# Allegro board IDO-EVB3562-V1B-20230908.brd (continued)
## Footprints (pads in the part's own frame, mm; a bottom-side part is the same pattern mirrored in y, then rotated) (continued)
RJ45-TH_HR911105A
  round 3.25 hole 3.25 unplated: (-5.715,0) (5.715,0)
  round 1.27 hole 0.914: 1(-4.445,6.35) 2(-3.175,8.89) 3(-1.905,6.35) 4(-0.635,8.89) 5(0.635,6.35) 6(1.905,8.89) 7(3.175,6.35) 8(4.445,8.89) 9(-6.625,-4.9) 10(-4.085,-4.9) 11(4.085,-4.9) 12(6.625,-4.9)
  round 2.5 hole 1.7: 13(-7.745,3.05) 14(7.745,3.05)
RJ45-TH_HY911130A
  round 2.997 hole 3.251 unplated: (-5.715,0) (5.715,0)
  round 1.524 hole 0.889: 1(5.715,-8.89) 2(4.445,-6.35) 3(3.175,-8.89) 4(1.905,-6.35) 5(0.635,-8.89) 6(-0.635,-6.35) 7(-1.905,-8.89) 8(-3.175,-6.35) 9(-4.445,-8.89) 10(-5.715,-6.35)
  round 1.651 hole 1.016: 11(6.624,4.9) 12(4.084,4.9) 13(-4.084,4.9) 14(-6.624,4.9)
  round 2.54 hole 1.651: SH1(-7.846,-3.051) SH2(7.846,-3.051)
RN_0402X4
  rect 0.5x0.399 smd: 1(-0.5,0.8) 4(-0.5,-0.8) 5(0.5,-0.8) 8(0.5,0.8)
  rect 0.5x0.3 smd: 2(-0.5,0.25) 3(-0.5,-0.25) 6(0.5,-0.25) 7(0.5,0.25)
SIM-91288-021
  rect 1.829x1.397 smd: C1(-0.251,12.319) C2(-0.251,9.779) C3(-0.251,7.239) C5(-23.422,12.319) C6(-23.422,9.779) C7(-23.422,7.239) CD1(-0.251,-0.051) CD2(-23.422,-0.051)
SIP2-10D-510
  round 1.4 hole 0.991: 1(-2.591,0) 2(2.591,0)
SMAF
  rect 1.43x1.53 smd: A(-1.84,0) C(1.84,0)
SMB_DO-214AA
  rect 1.65x1.95 smd: A(2.2,0) C(-2.2,0)
SMD1812
  rect 2.032x3.302 smd: 1(-2.159,0) 2(2.159,0)
SOD523
  rect 0.65x0.5 smd: A(0.9,0) C(-0.9,0)
SOD-123F
  rect 0.94x0.95 smd: A(-1.55,0) C(1.55,0)
SOM3562-182P
  oval 1.4x0.66 smd: 1(44.8,1.5) 2(44.8,2.5) 3(44.8,3.5) 4(44.8,4.5) 5(44.8,5.5) 6(44.8,6.5) 7(44.8,7.5) 8(44.8,8.5) 9(44.8,9.5) 10(44.8,10.5) 11(44.8,11.5) 12(44.8,12.5) 13(44.8,13.5) 14(44.8,14.5) 15(44.8,15.5) 16(44.8,16.5) 17(44.8,17.5) 18(44.8,18.5) 19(44.8,19.5) 20(44.8,20.5) 21(44.8,21.5) 22(44.8,22.5) 23(44.8,23.5) 24(44.8,24.5) 25(44.8,25.5) 26(44.8,26.5) 27(44.8,27.5) 28(44.8,28.5) 29(44.8,29.5) 30(44.8,30.5) 31(44.8,31.5) 32(44.8,32.5) 33(44.8,33.5) 34(44.8,34.5) 35(44.8,35.5) 36(44.8,36.5) 37(44.8,37.5) 38(44.8,38.5) 39(44.8,39.5) 40(44.8,40.5) 41(44.8,41.5) 42(44.8,42.5) 43(44.8,43.5) 87(0.2,43.5) 88(0.2,42.5) 89(0.2,41.5) 90(0.2,40.5) 91(0.2,39.5) 92(0.2,38.5) 93(0.2,37.5) 94(0.2,36.5) 95(0.2,35.5) 96(0.2,34.5) 97(0.2,33.5) 98(0.2,32.5) 99(0.2,31.5) 100(0.2,30.5) 101(0.2,29.5) 102(0.2,28.5) 103(0.2,27.5) 104(0.2,26.5) 105(0.2,25.5) 106(0.2,24.5) 107(0.2,23.5) 108(0.2,22.5) 109(0.2,21.5) 110(0.2,20.5) 111(0.2,19.5) 112(0.2,18.5) 113(0.2,17.5) 114(0.2,16.5) 115(0.2,15.5) 116(0.2,14.5) 117(0.2,13.5) 118(0.2,12.5) 119(0.2,11.5) 120(0.2,10.5) 121(0.2,9.5) 122(0.2,8.5) 123(0.2,7.5) 124(0.2,6.5) 125(0.2,5.5) 126(0.2,4.5) 127(0.2,3.5) 128(0.2,2.5) 129(0.2,1.5)
  oval 0.66x1.4 smd: 44(43.5,44.8) 45(42.5,44.8) 46(41.5,44.8) 47(40.5,44.8) 48(39.5,44.8) 49(38.5,44.8) 50(37.5,44.8) 51(36.5,44.8) 52(35.5,44.8) 53(34.5,44.8) 54(33.5,44.8) 55(32.5,44.8) 56(31.5,44.8) 57(30.5,44.8) 58(29.5,44.8) 59(28.5,44.8) 60(27.5,44.8) 61(26.5,44.8) 62(25.5,44.8) 63(24.5,44.8) 64(23.5,44.8) 65(22.5,44.8) 66(21.5,44.8) 67(20.5,44.8) 68(19.5,44.8) 69(18.5,44.8) 70(17.5,44.8) 71(16.5,44.8) 72(15.5,44.8) 73(14.5,44.8) 74(13.5,44.8) 75(12.5,44.8) 76(11.5,44.8) 77(10.5,44.8) 78(9.5,44.8) 79(8.5,44.8) 80(7.5,44.8) 81(6.5,44.8) 82(5.5,44.8) 83(4.5,44.8) 84(3.5,44.8) 85(2.5,44.8) 86(1.5,44.8) 130(1.5,0.2) 131(2.5,0.2) 132(3.5,0.2) 133(4.5,0.2) 134(5.5,0.2) 135(6.5,0.2) 136(7.5,0.2) 137(8.5,0.2) 138(9.5,0.2) 139(10.5,0.2) 140(11.5,0.2) 141(12.5,0.2) 142(13.5,0.2) 143(14.5,0.2) 144(15.5,0.2) 145(16.5,0.2) 146(17.5,0.2) 147(18.5,0.2) 148(19.5,0.2) 149(20.5,0.2) 150(21.5,0.2) 151(22.5,0.2) 152(23.5,0.2) 153(24.5,0.2) 154(25.5,0.2) 155(26.5,0.2) 156(27.5,0.2) 157(28.5,0.2) 158(29.5,0.2) 159(30.5,0.2) 160(31.5,0.2) 161(32.5,0.2) 162(33.5,0.2) 163(34.5,0.2) 164(35.5,0.2) 165(36.5,0.2) 166(37.5,0.2) 167(38.5,0.2) 168(39.5,0.2) 169(40.5,0.2) 170(41.5,0.2) 171(42.5,0.2) 172(43.5,0.2)
  rect 1.6x1.6 smd: 173(41.19,3.81) 174(41.19,7.62) 175(41.19,11.43) 176(41.19,15.24) 177(41.19,19.05) 178(41.19,22.86) 179(41.19,26.67) 180(41.19,41.19) 181(3.81,41.19) 182(3.81,3.81)
SOP8-P127-390X490
  rect 1.35x0.55 smd: 1(-2.6,1.905) 2(-2.6,0.635) 3(-2.6,-0.635) 4(-2.6,-1.905) 5(2.6,-1.905) 6(2.6,-0.635) 7(2.6,0.635) 8(2.6,1.905)
SOP16-P127-390X990
  rect 1.905x0.635 smd: 1(0,0) 2(0,-1.27) 3(0,-2.54) 4(0,-3.81) 5(0,-5.08) 6(0,-6.35) 7(0,-7.62) 8(0,-8.89) 9(6.096,-8.89) 10(6.096,-7.62) 11(6.096,-6.35) 12(6.096,-5.08) 13(6.096,-3.81) 14(6.096,-2.54) 15(6.096,-1.27) 16(6.096,0)
SOT23
  rect 1.05x0.65 smd: 1(-1.15,0.95) 2(-1.15,-0.95) 3(1.15,0)
SOT23-5
  rect 1.1x0.6 smd: 1(-1.35,0.95) 2(-1.35,0) 3(-1.35,-0.95) 4(1.35,-0.95) 5(1.35,0.95)
SOT23-6
  rect 1.05x0.6 smd: 1(-1.35,0.95) 2(-1.35,0) 3(-1.35,-0.95) 4(1.35,-0.95) 5(1.35,0) 6(1.35,0.95)
SOT523
  rect 0.85x0.3 smd: 1(-0.8,0.5) 2(-0.8,-0.5) 3(0.8,0)
TF-01A
  round 0.1 hole 1: (-7.2,-10.5) (0.8,-10.5)
  oval 0.7x2.3 smd: 1(0,0.2) 2(-1.1,0.2) 3(-2.2,0.2) 4(-3.3,0.2) 5(-4.4,0.2) 6(-5.5,0.2) 7(-6.6,0.2) 8(-7.7,0.2) 9(-8.8,0.2)
  rect 1.2x1.4 smd: 10(-10,-0.5)
  rect 1.6x1.4 smd: 11(4.6,-0.5)
  rect 1.2x2.2 smd: 12(-10,-10.2) 13(5.5,-10.2)
TP100
  round 1 smd: 1(0,0)
TSSOP-16
  rect 1.45x0.45 smd: 1(-2.901,2.276) 2(-2.901,1.626) 3(-2.901,0.975) 4(-2.901,0.325) 5(-2.901,-0.325) 6(-2.901,-0.975) 7(-2.901,-1.626) 8(-2.901,-2.276) 9(2.901,-2.276) 10(2.901,-1.626) 11(2.901,-0.975) 12(2.901,-0.325) 13(2.901,0.325) 14(2.901,0.975) 15(2.901,1.626) 16(2.901,2.276)
unnamed
  round 1.016 smd: 1(0,0)
USB-9AF-DIP_2X
  round 1.118 hole 0.711: 1(-3.5,0) 2(-1,0) 3(1,0) 4(3.5,0) 5(4,1.5) 6(2,1.5) 7(0,1.5) 8(-2,1.5) 9(-4,1.5) 10(-3.5,3.2) 11(-1,3.2) 12(1,3.2) 13(3.5,3.2) 14(4,4.7) 15(2,4.7) 16(0,4.7) 17(-2,4.7) 18(-4,4.7)
  round 2.794 hole 2.362: 19(-6.57,3.68) 20(6.57,3.68) 21(6.57,-2) 22(-6.57,-2)
V0402
  rect 0.57x0.62 smd: 1(-0.48,0) 2(0.48,0)
XTAL_32X15_2P
  rect 0.85x1.6 smd: 1(-1.25,0) 2(1.25,0)
XTAL_32X25_4P
  rect 1.2x1.3 smd: 1(-0.9,1.2) 2(-0.9,-1.2) 3(0.9,-1.2) 4(0.9,1.2)

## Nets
GND: C1.2 C2.1 C3.1 C28.1 C29.1 C30.1 C32.1 C33.1 C34.1 C36.1 C37.1 C39.2 C40.2 C42.2 C43.2 C45.2 C46.2 C53.1 C54.2 C61.1 C62.1 C63.1 C65.1 C67.1 C68.1 C69.1 C70.1 C74.1 C75.1 C76.1 C77.1 C80.1 C81.1 C82.1 C85.1 C86.1 C87.1 C88.1 C89.1 C90.1 C91.1 C92.1 C93.1 C94.1 C95.1 C96.1 C97.1 C98.1 C99.1 C100.1 C101.1 C102.1 C103.1 C104.1 C105.1 C107.1 C108.1 C112.2 C113.2 C114.1 C115.2 C116.2 C126.2 C128.1 C129.1 C130.1 C131.1 C132.1 C133.1 C143.1 C147.1 C150.2 C151.1 C152.1 C155.1 C156.2 C158.1 C159.1 C160.1 C163.1 C164.1 C166.1 C167.1 C168.1 C169.1 C170.1 C171.1 C176.1 C180.1 C189.1 C190.2 C191.1 C207.1 C208.1 C209.1 C210.1 C211.1 C212.1 C213.1 C214.1 C216.2 C217.2 C220.2 C221.2 C223.1 C226.1 C227.1 C261.2 C262.2 C264.1 C265.1 C266.1 C267.1 C268.1 C269.1 C270.1 C271.1 C272.1 C273.1 C274.1 C275.1 C276.1 C277.1 C278.1 C279.1 C280.1 C281.1 C282.1 C283.1 C284.2 C285.1 C287.1 C288.1 C289.1 C291.1 C292.1 C293.1 C294.1 C295.1 C301.1 C302.1 C303.1 C304.1 C305.1 C306.1 C307.2 C308.2 C309.2 C310.1 C311.1 C312.1 C313.1 C314.1 C315.1 C316.1 C318.1 C320.1 C321.1 C322.1 C323.1 C324.1 C325.1 C326.1 C327.1 C328.1 C329.1 C330.1 C331.1 C332.1 C333.1 C334.1 C335.1 C336.1 C337.1 C338.1 C339.1 C340.1 C341.1 C342.1 C343.1 C344.1 C347.1 C348.1 C349.1 C350.1 C351.1 C352.1 C355.1 C356.1 C357.1 C358.1 C359.1 C360.1 C361.1 C362.1 C363.1 C364.1 C365.1 C366.1 C367.1 C368.1 C528.2 C530.2 C531.2 C532.2 C533.2 C806.2 C807.1 C808.1 C809.1 C811.2 C812.2 C813.2 C814.2 C870.2 C871.2 C1010.1 C1011.1 C1013.1 C1014.1 C1015.1 C1016.1 C1017.1 C1018.1 C1019.1 C1020.1 C1022.1 C1023.1 C1024.1 C1025.1 C1026.1 C1027.1 C1028.1 C1029.1 C1030.1 C1031.1 C1032.1 C1033.1 C1035.1 C1036.1 C1037.1 C1038.1 C1040.1 C1041.1 C1042.1 C1044.1 C1045.1 C1046.1 C1047.1 D3.A D4.1(I/O2) D5.2(I/O1) D6.1(I/O2) D7.2(I/O1) D8.1(I/O2) D9.2(I/O1) D20.3 D20.8 D21.3 D21.8 D24.3 D24.8 D33.2 D34.2 D35.2 D36.2 D37.1(I/O2) D38.1(I/O2) D39.1(I/O2) D40.1(I/O2) D41.1(I/O2) D42.1(I/O2) D46.2(I/O1) D50.2(I/O1) D51.2(I/O1) D65.2(I/O1) D66.2(I/O1) D67.2(I/O1) D68.2(I/O1) D69.2(I/O1) D79.C(I/O1) D80.2 D194.C(I/O1) D195.C(I/O1) J1.2 J1.3 J1.5(TH1) J1.6(TH2) J2.1(3) J2.2 J2.3(1) J3.1(3) J3.2 J3.3(1) J4.1(3) J4.2 J4.3(1) J5.1(3) J5.2 J5.3(1) J6.6(VSS) J6.10(G1) J6.11(G2) J6.12(G3) J6.13(G4) J7.4 J8.4 J10.4(GND#4) J10.9(GND#9) J10.15(GND#15) J10.18(GND#18) J10.21(GND#21) J10.26(GND#26) J10.27(GND#27) J10.29(GND#29) J10.34(GND#34) J10.35(GND#35) J10.37(GND#37) J10.40(GND#40) J10.43(GND#43) J10.50(GND#50) J10.55(MT3) J10.56(MT4) J11.C5(GND) J13.6 J13.7 J13.8 J16.5 J16.6 J16.13 J16.14 J18.1 J18.4 J18.7 J18.10 J18.13 J18.16 J18.18 J18.23 J18.25 J18.31 J18.32 J19.10 J19.13 J19.16 J19.19 J19.22 J19.25 J19.26 J20.6 J20.12 J20.16 J20.19 J20.27 J20.29 J20.30 J20.31 J20.32 J20.33 J20.34 J21.10(GND) J22.10(GND) J23.8(P8) J24.1(GND1) J24.3(GND2) J24.4(GND3) J27.1(GND#1) J27.3(GND#3) J27.9(GND#9) J27.15(GND#15) J27.21(GND#21) J27.27(GND#27) J27.33(GND#33) J27.39(GND#39) J27.45(GND#45) J27.51(GND#51) J27.57(GND#57) J27.71(GND#71) J27.73(GND#73) J27.75(GND#75) J27.G1(EHT1) J27.G2(EHT2) J27.G3(G4) J27.G4(G3) J28.3 J28.4 J28.5 J36.2 J36.3 J36.4 J42.4(GND1) J42.7(GND2) J42.13(GND3) J42.16(GND4) J42.19(SHELL1) J42.20(SHELL2) J42.21(SHELL3) J42.22(SHELL4) J43.1 J43.2 J44.19 J45.6 J45.7 J45.8 J46.1 J46.4 J46.7 J46.10 J46.13 J46.25 J46.26 J47.2 J48.1(3) J48.2 J48.3(1) J49.1(3) J49.2 J49.3(1) J50.1(3) J50.2 J50.3(1) J51.1(3) J51.2 J51.3(1) J54.4 J55.4 J56.4 M1.3(GND3) M1.30(GND30) M1.55(GND55) M1.75(GND75) M1.95(GND95) M1.117(GND117) M1.152(GND152) M1.173(GND173) M1.180(GND180) M1.181(GND181) M1.182(GND182) M6.1 Q1.2(SOURCE) Q4.2(SOURCE) Q5.2(SOURCE) Q6.2(SOURCE) Q7.2(SOURCE) Q9.2(SOURCE) R10.1 R31.2 R34.2 R35.2 R47.2 R82.1 R133.1 R135.1 R137.1 R139.1 R158.1 R171.1 R174.1 R176.1 R179.1 R180.1 R181.1 R183.1 R184.1 R187.1 R193.2 R200.1 R209.2 R211.2 R216.2 R218.1 R220.2 R239.1 R244.1 R253.1 R306.2 R316.1 R341.2 R389.1 R412.1 R413.1 R414.2 R442.1 R446.2 R447.1 R459.2 R782.1 R785.1 R1060.2 R1067.1 R1070.1 R1169.1 R1177.2 R1178.2 R1192.2 R1198.1 R1202.2 SW4.2 SW4.3 SW5.1 SW5.2 SW5.3 SW6.1 SW6.2 SW6.3 U3.2(GND) U4.2(GND) U5.2(GND) U6.2(GND) U7.6(VSS) U7.10(VS_PLL) U7.16(VSS_1) U7.22(VSS-2) U7.25(VS_A) U7.33(VSS_3) U7.37(DIS_REG) U7.40(TEST) U8.1(VSS) U8.9(PAD) U9.2(GND) U10.2(GND) U11.2(GND) U12.2(GND) U13.2(GND) U14.2(GND) U15.33(GND) U16.41(E_PAD) U17.33(E-PAD) U18.1(GND1) U18.3(GND2) U18.20(GND3) U18.31(GND4) U18.33(GND5) U18.36(GND6) U20.4(VSS) U25.2(PGND1) U25.11(GND1) U25.15(PGND2) U29.2(GND) U42.15(GND) U43.2(GND) U59.6(GND) U70.1(GND#1) U70.3(GND#3) U71.2(GND) U72.2(GND) U73.2(GND) XT1.2 XT1.4 XT2.2 XT2.4 XT3.2 XT3.4 XT4.2 XT4.4 XT5.2 XT5.4
GND_EARTH: HOLE5.1 HOLE9.1 HOLE10.1 HOLE11.1 J21.SH1 J21.SH2 J22.SH1 J22.SH2 J23.13(P13) J23.14(P14)
VBAT_WL_1T1R: C176.2 C344.2 R241.2 U18.9(VBAT)
VCC1V2_DVP: C103.2 C104.2 C1023.2 C1030.2 C1048.2 J18.28 J20.22 R136.2 U13.5(VOUT)
VCC1V5_DVP: C107.2 C108.2 C369.2 C1026.2 J19.3 R138.2 U14.5(VOUT)
VCC1V8_DVP: C100.2 C101.2 C1024.2 C1027.2 C1029.2 J18.27 J19.4 J20.24 R113.2 R134.2 R417.2 U12.5(VOUT)
VCC2V8_DVP: C96.2 C98.2 C1028.2 J20.8 J20.25 R132.2 U11.5(VOUT)
VCC2V8_DVP1: C1015.2 C1016.2 C1022.2 J19.1 J19.2 R1066.2 U71.5(VOUT)
VCC2V8_DVP2: C1019.2 C1020.2 C1025.2 J18.24 J18.29 R1069.2 U72.5(VOUT)
VCC3V3_E: C1039.2 C1040.2 C1041.2 C1042.2 L29.1 L44.2 R1170.2
VCC3V3_PHY0: C333.2 C334.2 C335.2 C359.2 C360.2 R175.2 R189.2 R190.2 R194.2 U16.11(AVDD33#11) U16.29(DVDD33) U16.40(AVDD33#40)
VCC3V3_PHY2: C325.2 C326.2 C327.2 C363.2 R150.2 R156.1 R157.2 R160.2 R161.1 U15.11(AVDD33(NC)) U15.23(VDDREG(DVDD33)) U15.32(AVDD33)
VCC3V3_SD_OUT: C278.2 C287.2 J6.4(VDD) M1.9(VCC3V3_SD_OUT)
VCC3V3_SPK: C207.2 C208.2 C209.2 R299.2 U25.6(VDD1) U25.9(VDD2)
VCC3V3_SY8368: C814.1 U70.8(VCC)
VCC3V3_SYS: C31.2 C32.2 C33.2 C34.2 C36.2 C284.1 C365.2 C368.2 C1032.2 C1034.2 D48.A L3.2 Q10.2(SOURCE) R8.2 R62.1 R240.1 R241.1 R423.1 R431.1 R1080.2 R1084.1 R1174.2 R1211.1 U59.11(VCCB)
VCC5V0_HUB2: C45.1 J42.10(VBUS2) U6.1(VOUT)
VCC5V0_HUB3: C39.1 J7.1 U4.1(VOUT)
VCC5V0_HUB4: C42.1 J8.1 U5.1(VOUT)
VCC5V_SYS: C28.2 C29.2 C30.2 C40.1 C43.1 C46.1 C77.2 C262.1 C316.2 C806.1 C811.1 C812.1 C813.1 C815.1 C870.1 C871.1 C1010.2 C1012.2 C1037.2 C1038.2 C1044.2 L33.2 Q8.2(SOURCE) R17.2 R450.2 R451.2 R787.1 R1063.2 R1168.2 R1209.2 R1210.2 U3.4(VIN) U4.5(IN) U5.5(IN) U6.5(IN) U9.4(VIN) U29.5(IN) U73.4(VIN)
VCC_1V8_OUT: C92.2 J46.17 J46.18 M1.17(VCC_1V8_OUT) R13.1 R14.1 R15.1 R16.1 R382.1 R444.2 R1078.1 R1197.2
VCC_3V3: C91.2 C97.2 C99.2 C102.2 C105.2 C226.2 C1013.2 C1017.2 C1033.2 C1036.2 J15.5 J46.19 J46.20 L12.1 Q10.3(DRAIN) R19.1 R48.2 R160.1 R194.1 R261.2 R299.1 R314.2 R318.1 R415.1 R425.1 R426.1 R437.2 R460.2 R465.1 R466.1 R1077.1 R1084.2 R1181.2 R1201.2 U11.1(VIN) U12.1(VIN) U13.1(VIN) U14.1(VIN) U42.16(VCC) U71.1(VIN) U72.1(VIN)
VCC_3V3_OUT: M1.7(VCC_3V3_OUT) R11.1 R12.1 R383.1 R384.1 R391.2
VCC_DCIN: F3.1 F4.1 J1.4 J15.1 J43.5 J43.6
VCC_DMIC: C227.2 J45.1 R318.2
VCC_LEDA+: C89.2 C90.2 C1031.2 D18.C J46.23 J46.24 U10.5(OVP)
VCC_LEDK-: J46.21 J46.22 R84.2 R412.2 R413.2
VCC_M2: C289.2 C291.2 C292.2 C293.2 C294.2 C295.2 C301.2 C348.2 C349.2 C350.2 C351.2 C352.2 J27.2(3.3V#2) J27.4(3.3V#4) J27.12(3.3V#12) J27.14(3.3V#14) J27.16(3.3V#16) J27.18(3.3V#18) J27.70(3.3V#70) J27.72(3.3V#72) J27.74(3.3V#74) L29.2
VCC_OUT: C264.2 C1046.2 C1047.2 J44.1 J54.1 J55.1 J56.1 R366.2 R1077.2
VCC_RMII: C159.2 C164.2 C338.2 L11.1 L12.2 R195.2 R204.2 R205.1 R207.1 R212.2 R217.2 R219.1 R1200.2 U17.14(DVDD33)
VCC_SIM: C65.2 C314.2 C315.2 J11.C1(VDD) R52.2 R53.2 R440.2 U8.8(VDD)
VCC_SYS: C1.1 C2.2 C3.2 C807.2 C808.2 C809.2 D1.C D2.C R783.1 U70.4(IN#4) U70.5(IN#5) U70.6(IN#6)
VCC_TP: C285.2 R421.2 R422.2 R423.2 R448.2 R449.2 R1197.1 U59.1(VCCA)
VCCA_RMII: C160.2 C336.2 C337.2 L11.2 U17.7(AVDD33_1) U17.30(AVDD33_2)
VCCIO4_IN: C271.2 M1.31(VCCIO4_IN) R384.2
VCCIO5_IN: C270.2 M1.76(VCCIO5_IN) R383.2
VCCIO6_IN: C269.2 M1.116(VCCIO6_IN) R382.2
VCCIO_PHY0: C358.2 C361.2 R178.2 R182.2 R185.2 R188.2 R191.2 U16.28(DVDD_RG)
VCCIO_WL: C342.2 C366.2 R240.2 U18.22(VDDIO)
VDD10_PHY0: C328.2 C329.2 C330.2 C331.2 C332.2 C357.2 L31.2 U16.3(AVDD10#3) U16.8(AVDD10#8) U16.21(DVDD10) U16.38(AVDD10#38)
VDD10_PHY2: C320.2 C362.2 L32.2 R159.1 R1064.2
VDD10_RTL: C126.1 C321.2 C322.2 C323.2 C324.2 R159.2 U15.3(AVDD10(NC)) U15.8(AVDD10_0) U15.22(DVDD10(NC)) U15.30(AVDD10_1)
VDD_3V8: C67.2 C68.2 C69.2 C70.2 C74.2 C75.2 C76.2 C79.2 C80.2 C81.2 C312.2 C313.2 J10.2(VCC3V3#2) J10.24(NC3) J10.39(VCC3V3#39) J10.41(VCC3V3#41) J10.52(VCC3V3#52) L7.2 R60.2 R452.2
VDD_5V: C85.2 C87.2 C213.2 C532.1 C1011.2 J15.3 L8.1 Q8.3(DRAIN) R300.2 R366.1 U10.6(VIN) U43.3(VCC)
VDD_LCD: C84.2 C86.2 J15.2 J15.4 Q3.2(SOURCE) R80.2
VDD_LCD_: C88.2 J16.1 J16.2 J16.3 Q3.3(DRAIN)
VDD_RTC: C190.1 D48.C D49.C U20.8(VDD)
4G_DM: J10.36(USB_D-) R49.2
4G_DP: J10.38(USB_D+) R50.2
4G_LED_WANN#: J10.42(LED_WWAN) LED2.C(CATHODE)
4G_POWER_H: M1.108(UART6_RX_M1/PDM_SDI1_M1/UART1_C) R441.1
ADC0: J44.10 R350.2
ADC1: J44.12 R349.2
ADC2: J44.14 R348.2
ADC3: J44.16 R347.2
ADC4: J44.18 R346.2
ADC5: J44.20 R345.2
AF-PWDN: J20.26 R416.2
BATDIV: M1.176(BATDIV) TP3.1
BT_REG_ON_H: R235.2 R245.1
BT_REG_ON_H_GPIO0_B0_D: M1.167(PCIE20_BUTTONRSTN/CLK0_32K_OUT/) R235.1
CAM_CLK0_OUT_M1: M1.109(I2S2_SCLK_M1/CAM_CLK0_OUT_M1/PD) R123.1
CAM_CLK2_OUT: M1.84(PWM12_M1/SPI0_MOSI_M1/UART8_CTS) R1179.1
CAM_CLK3_OUT: M1.83(PWM13_M1/SPI0_CLK_M1/UART8_RTSN) R1180.1
CAN0_H: D194.A(I/O2) J56.2 L45.2
CAN0_L: D195.A(I/O2) J56.3 L46.2
CAN0_RX_M2: R1208.2 U43.4(RXD)
CAN0_STB_IO: R459.1 U43.8(S)
CAN0_TX_M2: R1207.2 U43.1(TXD)
CAN0H: L45.1 R462.1 U43.7(CANH)
CAN0L: L46.1 R461.1 U43.6(CANL)
CIF1_SCL: J18.21 R126.2
CIF1_SDA: J18.22 R127.2
CIF2_RST: C288.2 J20.5 R372.2 R417.1
CIF2_RST_L: M1.88(PWM14_M0/UART4_CTSN_M0/I2S1_SCL) R372.1
CIF2_SCL: J19.7 J20.21 R128.2
CIF2_SDA: J19.8 J20.23 R129.2
CIF_EN: R130.1 R373.1 R374.1 R375.1 R1065.1 R1068.1 R1172.2 R1181.1
CIF_PDN: J18.19 J19.6 J20.20 R124.2 R416.1
CIF_PDN_L: M1.89(PWM15_M0/UART4_RTSN_M0/I2S1_LRC) R124.1
CIF_PWREN_H: M1.87(UART7_TX_M0/I2S1_MCLK_M0/VO_LCD) R78.2 R1082.2 R1172.1
CIF_RST: C94.2 J18.20 J19.5 R113.1 R125.2
CIF_RST_L: M1.90(UART7_RX_M0/I2S1_SDO0_M0/VO_LCD) R125.1
CKXTALIN: C156.1 U17.32(CKXTAL-IN) XT4.3
CKXTALOUT: C158.2 U17.31(CKXTAL-OUT) XT4.1
CLKREQB: R155.2 U15.12(CLKREQB)
CSI0_MCLK: C95.2 J20.14 R123.2
CSI2_MCLK: J19.9 R1177.1 R1179.2
CSI3_MCLK: J18.17 R1178.1 R1180.2
GMAC0_TXCLK_: C132.2 R177.2 U16.20(TXC)
GMAC1_RSTN: C364.2 R172.2 R190.1 U16.12(PHYRSTB)
GMAC1_RSTN_GPIO0_A6_D: M1.169(PCIE20_CLKREQN_M0/GPIO0_A6_D) R172.1
GPIO0_A5_D: M1.170(PMU_DEBUG/I2C4_SCL_M1/SDMMC0_PW) R429.2 R430.2
HOST_WAKE_BT_H: R237.2 R1174.1 U18.6(BT_WAKE)
HOST_WAKE_BT_H_GPIO0_A7_D: M1.168(PWM3_M0/GPIO0_A7_D) R237.1 R1173.2
HP_DET_L_GPIO0_B3_D: M1.153(I2C1_SCL_M0/GPIO0_B3_D) R455.1
HP_SNS: J37.4(MIC) M1.11(HP_SNS) R306.1 R316.2
HPL_OUT: C215.1 C222.2 M1.10(HPL_OUT)
HPL_OUT+: C222.1 D66.1(I/O2) J37.2(L) R447.2
HPR_OUT: C219.1 C224.2 M1.12(HPR_OUT)
HPR_OUT+: C224.1 D68.1(I/O2) J37.3(R)
HUB_1V8: C303.2 C305.2 C310.2 C355.2 U7.3(VD18_1) U7.9(VD_PLL) U7.26(VREG18) U7.29(VD18)
HUB_3V3: C304.2 C306.2 C307.1 C308.1 C309.1 C356.2 R45.2 R48.1 R434.1 R435.1 R436.1 R438.2 R439.2 U7.13(VDD33_1) U7.19(VDD33_2) U7.27(VD3_IN) U7.32(VDD33_3) U7.39(VD33_OUT) U7.41(VDD33_4)
HUB_DM1: R49.1 U7.23(DM1)
HUB_DM2: R37.1 U7.20(DM2)
HUB_DM2_2: D8.2(I/O1) J42.11(2D-) R37.2
HUB_DM3: R29.1 U7.17(DM3)
HUB_DM3_2: D4.2(I/O1) J7.2 R29.2
HUB_DM4: R32.1 U7.14(DM4)
HUB_DM4_2: D6.2(I/O1) J8.2 R32.2
HUB_DP1: R50.1 U7.24(DP1)
HUB_DP2: R38.1 U7.21(DP2)
HUB_DP2_2: D9.1(I/O2) J42.12(2D+) R38.2
HUB_DP3: R30.1 U7.18(DP3)
HUB_DP3_2: D5.1(I/O2) J7.3 R30.2
HUB_DP4: R33.1 U7.15(DP4)
HUB_DP4_2: D7.1(I/O2) J8.3 R33.2
HUB_REXT: R47.1 U7.28(REXT)
HUB_VBUSM: R437.1 U7.35(VBUSM)
HUB_XIN: C54.1 R43.2 U7.12(XIN) XT1.3
HUB_XOUT: C53.2 R43.1 U7.11(XOUT) XT1.1
HUB_XRSTJ: C311.2 R36.2 R45.1 U7.34(XRSTJ)
I2C1_SCL_M1: M1.112(UART3_TX_M0/I2C1_SCL_M1/SPI2_CS) R15.2 R128.1
I2C1_SDA_M1: M1.113(UART3_RX_M0/I2C1_SDA_M1/SPI2_CS) R16.2 R129.1
I2C2_SCL_M1: M1.93(I2C2_SCL_M1/SPI2_MISO_M0/UART7_) R13.2 R126.1
I2C2_SDA_M1: M1.94(I2C2_SDA_M1/SPI2_MOSI_M0/UART7_) R14.2 R127.1
I2C3_SCL_M0: M1.71(UART5_CTSN_M1/PDM_SDI3_M0/UART2) R12.2 R343.1 U59.9(B2)
I2C3_SDA_M0: M1.70(UART5_RTSN_M1/SPDIF_TX_M0/UART2) R11.2 R344.1 U59.10(B1)
I2C5_SCL_M0/UART9_TX_M1: J44.15 R365.6 R425.2
I2C5_SDA_M0/UART9_RX_M1: J44.17 R365.5 R426.2
ILMT: R785.2 U70.10(ILMT)
ISOLATEB: R156.2 U15.20(ISOLATEB)
LAN0_A+: D36.6 J22.2(MDI_0+) R169.2
LAN0_A-: D36.1 J22.3(MDI_0-) R168.2
LAN0_B+: D36.3 J22.4(MDI_1+) R167.2
LAN0_B-: D36.4 J22.7(MDI_1-) R166.2
LAN0_C+: D35.6 J22.5(MDI_2+) R165.2
LAN0_C-: D35.1 J22.6(MDI_2-) R164.2
LAN0_D+: D35.3 J22.8(MDI_3+) R163.2
LAN0_D-: D35.4 J22.9(MDI_3-) R162.2
LANWAKEB: R154.2 R161.2 U15.21(LANWAKEB)
LCD_BL_PWM_GPIO0_B7_D: M1.157(SPDIF_TX_M1/CPU_AVS/PWM4_M0/SPI) R75.1 R99.1
LCD_ON: J43.4 R98.2 R453.1
LCD_PWM: J43.3 R99.2
LCD_PWREN_H_GPIO0_B4_D: M1.154(I2C1_SDA_M0/GPIO0_B4_D) R98.1
LED0/PHYAD0: C152.2 J23.11(Y-) R205.2 U17.24(LED0/PHYAD0/PMEB)
LED1/GPO: C112.1 J21.13(Y_LED-) U15.26(LED1/GPO)
LED1/PHYAD1: C150.1 J23.9(G+) R200.2 U17.25(LED1/PHYAD1)
LED2/LED1: C113.1 J21.12(G_LED-) U15.25(LED2(LED1))
MAC_MDC_: C151.2 R203.2 U17.22(MDC)
MAC_MDIO: R202.2 R207.2 U17.23(MDIO)
MIC1_IN: C1049.2 D65.1(I/O2) J36.1 R388.2
MIC2_IN: C1050.2 D69.1(I/O2) J37.1(GND) R387.2
MIPI_CSI1_RX0_D2N: J19.11 R1175.5
MIPI_CSI1_RX0_D2P: J19.12 R1175.6
MIPI_CSI1_RX0_D3N: J19.14 R1175.7
MIPI_CSI1_RX0_D3P: J19.15 R1175.8
MIPI_CSI2_RX0_D2N: J18.11 R1176.8
MIPI_CSI2_RX0_D2P: J18.12 R1176.7
MIPI_CSI2_RX0_D3N: J18.14 R1176.6
MIPI_CSI2_RX0_D3P: J18.15 R1176.5
MIPI_CSI_RX0_CLK0N: J18.5 M1.137(MIPI_CSI_RX0_CLK0N)
MIPI_CSI_RX0_CLK0P: J18.6 M1.136(MIPI_CSI_RX0_CLK0P)
MIPI_CSI_RX0_CLK1N: J19.17 M1.131(MIPI_CSI_RX0_CLK1N)
MIPI_CSI_RX0_CLK1P: J19.18 M1.130(MIPI_CSI_RX0_CLK1P)
MIPI_CSI_RX0_D0N: J18.2 M1.141(MIPI_CSI_RX0_D0N)
MIPI_CSI_RX0_D0P: J18.3 M1.140(MIPI_CSI_RX0_D0P)
MIPI_CSI_RX0_D1N: J18.8 M1.139(MIPI_CSI_RX0_D1N)
MIPI_CSI_RX0_D1P: J18.9 M1.138(MIPI_CSI_RX0_D1P)
MIPI_CSI_RX0_D2N: M1.135(MIPI_CSI_RX0_D2N) R1175.4 R1176.1
MIPI_CSI_RX0_D2P: M1.134(MIPI_CSI_RX0_D2P) R1175.3 R1176.2
MIPI_CSI_RX0_D3N: M1.133(MIPI_CSI_RX0_D3N) R1175.2 R1176.3
MIPI_CSI_RX0_D3P: M1.132(MIPI_CSI_RX0_D3P) R1175.1 R1176.4
MIPI_CSI_RX1_CLK0N: J20.17 M1.125(MIPI_CSI_RX1_CLK0N)
MIPI_CSI_RX1_CLK0P: J20.15 M1.124(MIPI_CSI_RX1_CLK0P)
MIPI_CSI_RX1_CLK1N: M1.119(MIPI_CSI_RX1_CLK1N)
MIPI_CSI_RX1_CLK1P: M1.118(MIPI_CSI_RX1_CLK1P)
MIPI_CSI_RX1_D0N: J20.13 M1.129(MIPI_CSI_RX1_D0N)
MIPI_CSI_RX1_D0P: J20.11 M1.128(MIPI_CSI_RX1_D0P)
MIPI_CSI_RX1_D1N: J20.9 M1.127(MIPI_CSI_RX1_D1N)
MIPI_CSI_RX1_D1P: J20.7 M1.126(MIPI_CSI_RX1_D1P)
MIPI_CSI_RX1_D2N: J20.3 M1.123(MIPI_CSI_RX1_D2N)
MIPI_CSI_RX1_D2P: J20.1 M1.122(MIPI_CSI_RX1_D2P)
MIPI_CSI_RX1_D3N: J20.4 M1.121(MIPI_CSI_RX1_D3N)
MIPI_CSI_RX1_D3P: J20.2 M1.120(MIPI_CSI_RX1_D3P)
MIPI_DSI_RST: C93.2 D24.4 D24.5 D24.6 D24.7 J46.16 R78.1 R444.1
MIPI_DSI_TX_CLKN/LVDS_TX_CLKN: D21.4 D21.7 J16.15 M1.147(MIPI_DSI_TX_CLKN/LVDS_TX_CLKN) R1186.1
MIPI_DSI_TX_CLKP/LVDS_TX_CLKP: D21.5 D21.6 J16.16 M1.146(MIPI_DSI_TX_CLKP/LVDS_TX_CLKP) R1187.1
MIPI_DSI_TX_D0N/LVDS_TX_D0N: D20.1 D20.10 J16.7 M1.151(MIPI_DSI_TX_D0N/LVDS_TX_D0N) R1182.1
MIPI_DSI_TX_D0P/LVDS_TX_D0P: D20.2 D20.9 J16.8 M1.150(MIPI_DSI_TX_D0P/LVDS_TX_D0P) R1183.1
MIPI_DSI_TX_D1N/LVDS_TX_D1N: D20.4 D20.7 J16.9 M1.149(MIPI_DSI_TX_D1N/LVDS_TX_D1N) R1184.1
MIPI_DSI_TX_D1P/LVDS_TX_D1P: D20.5 D20.6 J16.10 M1.148(MIPI_DSI_TX_D1P/LVDS_TX_D1P) R1185.1
MIPI_DSI_TX_D2N/LVDS_TX_D2N: D21.1 D21.10 J16.11 M1.145(MIPI_DSI_TX_D2N/LVDS_TX_D2N) R1188.1
MIPI_DSI_TX_D2P/LVDS_TX_D2P: D21.2 D21.9 J16.12 M1.144(MIPI_DSI_TX_D2P/LVDS_TX_D2P) R1189.1
MIPI_DSI_TX_D3N/LVDS_TX_D3N: D24.2 D24.9 J16.17 M1.143(MIPI_DSI_TX_D3N/LVDS_TX_D3N) R1190.1
MIPI_DSI_TX_D3P/LVDS_TX_D3P: D24.1 D24.10 J16.18 M1.142(MIPI_DSI_TX_D3P/LVDS_TX_D3P) R1191.1
MIPI_TX_BL_PWM: R75.2 R82.2 U10.4(EN/PWM)
MIPI_TX_CLKN: J46.8 R1186.2
MIPI_TX_CLKP: J46.9 R1187.2
MIPI_TX_D0N: J46.2 R1182.2
MIPI_TX_D0P: J46.3 R1183.2
MIPI_TX_D1N: J46.5 R1184.2
MIPI_TX_D1P: J46.6 R1185.2
MIPI_TX_D2N: J46.11 R1188.2
MIPI_TX_D2P: J46.12 R1189.2
MIPI_TX_D3N: J46.14 R1190.2
MIPI_TX_D3P: J46.15 R1191.2
PA_5V: C210.2 C211.2 C212.2 R300.1 U25.4(PVDD1) U25.13(PVDD2)
PCIE20_0_TXN: C317.2 U15.14(HSIN)
PCIE20_0_TXP: C319.2 U15.13(HSIP)
PCIE20_32KHZ: J27.68(SUSCLK(32KHZ)(I)(3.3V)) R342.2
PCIE20_CLKREQN: J27.52(PCIE_CLKREQ#(IO)(3.3V)) R258.2
PCIE20_CLKREQN_M1: M1.72(PCIE20_CLKREQN_M1/UART5_TX_M1/P) R155.1 R258.1 R308.1
PCIE20_PERSTN: J27.50(PCIE_PERST#(I)(3.3V)) R260.2
PCIE20_PERSTN_M1: M1.74(PCIE20_PERSTN_M1/PDM_SDI1_M0/I2) R153.1 R260.1 R311.1
PCIE20_REFCLKN: M1.29(PCIE20_REFCLKN) R404.1 R408.1
PCIE20_REFCLKN_: J27.53(REFCLKN) R408.2
PCIE20_REFCLKP: M1.28(PCIE20_REFCLKP) R403.1 R407.1
PCIE20_REFCLKP_: J27.55(REFCLKP) R407.2
PCIE20_RXDN: J27.41(PETN0/SATA-B+) R406.2
PCIE20_RXDP: J27.43(PETP0/SATA-B-) R405.2
PCIE20_TXDN: C354.1 J27.47(PERN0/SATA-A-)
PCIE20_TXDP: C353.1 J27.49(PERP0/SATA-A+)
PCIE20_WAKEN: J27.54(PCIE_PEWAKE#(IO)(3.3V)) R259.2
PCIE20_WAKEN_M1: M1.73(PCIE20_WAKEN_M1/UART5_RX_M1/PDM) R154.1 R259.1 R310.1
PCIE_0_RXN: R402.2 U15.18(HSON)
PCIE_0_RXP: R401.2 U15.17(HSOP)
PDM_CLK0_M0: J45.3 R308.2
PDM_SDI1_M0: J45.5 R311.2
PDM_SDI2_M0: J45.4 R310.2
PERSTB: C318.2 R153.2 U15.19(PERSTB)
PHY0_CLKOUT125: R170.2 U16.35(CLKOUT)
PHY0_LED0/CFG_EXT: R174.2 U16.32(LED0/CFG_EXT)
PHY0_LED1/CFG_LDO0: C133.2 J22.14(Y_LED+) R176.2 U16.33(LED1/CFG_LDO0)
PHY0_LED2/CFG_LDO1: C131.2 J22.12(G_LED-) R175.1 U16.34(LED2/CFG_LDO1)
PHY0_MDI0+: R169.1 U16.1(MDI[0]+)
PHY0_MDI0-: R168.1 U16.2(MDI[0]-)
PHY0_MDI1+: R167.1 U16.4(MDI[1]+)
PHY0_MDI1-: R166.1 U16.5(MDI[1]-)
PHY0_MDI2+: R165.1 U16.6(MDI[2]+)
PHY0_MDI2-: R164.1 U16.7(MDI[2]-)
PHY0_MDI3+: R163.1 U16.9(MDI[3]+)
PHY0_MDI3-: R162.1 U16.10(MDI[3]-)
PHY0_REG_OUT: L31.1 U16.30(REG_OUT)
PHY0_RXCLK/PHYAD1: R179.2 R192.1 U16.27(RXC/PHYAD1)
PHY0_XTALIN: C129.2 U16.36(XTAL_IN) XT3.3
PHY0_XTALOUT: C128.2 U16.37(XTAL_OUT/EXT_CLK) XT3.1
PHY2_MDI0+: R145.1 U15.1(MDIP0)
PHY2_MDI0-: R144.1 U15.2(MDIN0)
PHY2_MDI1+: R149.1 U15.4(MDIP1)
PHY2_MDI1-: R148.1 U15.5(MDIN1)
PHY2_MDI2+: R142.1 U15.6(MDIP2(NC))
PHY2_MDI2-: R141.1 U15.7(MDIN2(NC))
PHY2_MDI3+: R147.1 U15.9(MDIP3(NC))
PHY2_MDI3-: R140.1 U15.10(MDIN3(NC))
PHY2_MDI_0+: D34.4 J21.2(MDI_0+) R145.2
PHY2_MDI_0-: D34.3 J21.3(MDI_0-) R144.2
PHY2_MDI_1+: D34.6 J21.4(MDI_1+) R149.2
PHY2_MDI_1-: D34.1 J21.7(MDI_1-) R148.2
PHY2_MDI_2+: D33.4 J21.5(MDI_2+) R142.2
PHY2_MDI_2-: D33.3 J21.6(MDI_2-) R141.2
PHY2_MDI_3+: D33.6 J21.8(MDI_3+) R147.2
PHY2_MDI_3-: D33.1 J21.9(MDI_3-) R140.2
PHY2_REG_OUT: L32.1 R1064.1 U15.24(REGOUT(NC))
PHY2_XTALIN: C116.1 U15.28(CKXTAL1) XT2.3
PHY2_XTALOUT: C115.1 U15.29(CKXTAL2) XT2.1
PHY_INT: R195.1 U17.11(RXD2/INTB)
PMIC_32KOUT_WIFI: M1.16(PMIC_32KOUT_WIFI) R243.1 R342.1 R391.1
PMIC_EXT_EN: M1.8(PMIC_EXT_EN) R4.1 R9.1 R1171.1
PMIC_PWRON: M1.4(PMIC_PWRON) R267.1
PMIC_SLEEP_H: M1.15(PMIC_SLEEP_H_OUT) R1083.1
PMIC_VDC: C302.2 M1.5(PMIC_VDC) R17.1 R389.2
PWRON_KEY: D51.1(I/O2) R267.2 SW4.1
RECOVERY_KEY: D46.1(I/O2) R264.2 SW5.4
REFCLKN_100M_RJ45: R404.2 U15.16(REFCLK_N)
REFCLKP_100M_RJ45: R403.2 U15.15(REFCLK_P)
RESET_KEY: D50.1(I/O2) R266.2 SW6.4
RESETN: M1.6(RESETN) R36.1 R266.1
RGMII_CLK_M0: C130.2 M1.115(CAM_CLK1_OUT_M1/PDM_CLK0_M1/RGM) R170.1 R171.2
RGMII_MDC_M0: M1.110(UART9_TX_M0/RGMII_MDC_M0/VO_LCD) U16.13(MDC)
RGMII_MDIO_M0: M1.111(UART9_RX_M0/RGMII_MDIO_M0/VO_LC) R191.1 U16.14(MDIO)
RGMII_RXCLK_M0: C143.2 M1.101(I2S2_LRCK_M1/PWM12_M0/RGMII_RXC) R192.2
RGMII_RXD0_M0: M1.105(I2C3_SCL_M1/PDM_SDI2_M1/UART1_T) R181.2 R182.1 U16.25(RXD0/RXDLY)
RGMII_RXD1_M0: M1.106(I2C3_SDA_M1/PDM_SDI3_M1/UART1_R) R184.2 R185.1 U16.24(RXD1/TXDLY)
RGMII_RXD2_M0: M1.99(SPI1_CSN0_M0/UART8_CTSN_M1/RGMI) R187.2 R188.1 U16.23(RXD2/PLLOFF)
RGMII_RXD3_M0: M1.100(SPI1_CSN1_M0/UART8_RTSN_M1/RGMI) R178.1 U16.22(RXD3/PHYAD0)
RGMII_RXDV_M0: M1.107(UART6_TX_M1/PDM_SDI0_M1/UART1_R) R180.2 U16.26(RXCTL/PHYAD2)
RGMII_TXCLK_M0: M1.98(I2S2_MCLK_M1/SPI1_CLK_M0/RGMII_) R177.1
RGMII_TXD0_M0: M1.102(UART6_CTSN_M1/SPI1_MOSI_M0/RGMI) U16.18(TXD0)
RGMII_TXD1_M0: M1.103(UART6_RTSN_M1/SPI1_MISO_M0/RGMI) U16.17(TXD1)
RGMII_TXD2_M0: M1.96(I2S2_SDI_M1/UART8_TX_M1/RGMII_T) U16.16(TXD2)
RGMII_TXD3_M0: M1.97(I2S2_SDO_M1/UART8_RX_M1/RGMII_T) U16.15(TXD3)
RGMII_TXEN_M0: M1.104(PWM13_M0/RGMII_TXEN_M0/VO_LCDC_) U16.19(TXCTL)
RMII_CLK: C155.2 M1.36(RMII_CLK/SPI2_CSN1_M1/UART4_RX_) R213.1
RMII_CLK_: R213.2 U17.15(TXC)
RMII_CLK_CTL: R216.1 U17.12(RXD3/CLK_CTL)
RMII_CRS_DV: M1.35(RMII_RXDV_CRS/SPI2_CSN0_M1/UART) R215.1 R1198.2
RMII_CRS_DVALID: R215.2 U17.26(CRS/CRS_DV)
RMII_MDC: M1.42(RMII_MDC/PWM2_M1/I2C5_SCL_M1/RG) R203.1
RMII_MDIO: M1.41(RMII_MDIO/PWM3_M1/I2C5_SDA_M1/R) R202.1
RMII_RST_: C340.2 R204.1 R208.2 U17.21(PHYRSTB)
RMII_RSTN: M1.32(CLK1_32K_OUT/SPI2_CLK_M1/I2S0_S) R208.1
RMII_RXD0: M1.37(RMII_RXD0/PWM7_M1/I2S0_SDI3_M1/) R197.2
RMII_RXD1: M1.34(RMII_RXD1/PWM14_M1/SPI2_MOSI_M1) R196.2
RMII_RXER: M1.33(RMII_RXER/PWM15_M1/SPI2_MISO_M1) R210.1
RMII_TXD0: M1.40(RMII_TXD0/PWM4_M1/I2S0_SDO1_M1/) R199.1
RMII_TXD0_: R199.2 U17.16(TXD0)
RMII_TXD1: M1.39(RMII_TXD1/PWM5_M1/I2S0_SDO2_M1/) R198.1
RMII_TXD1_: R198.2 U17.17(TXD1)
RMII_TXEN: M1.38(RMII_TXEN/PWM6_M1/I2S0_SDI2_M1/) R201.1
RMII_TXEN_: R201.2 U17.20(TXEN)
RN: R206.1 U17.6(MDI1-)
RP: R206.2 U17.5(MDI1+)
RS232_RX6: L42.1 U42.13(R1IN)
RS232_RX6_: J55.2 L42.2
RS232_RX8: L41.1 U42.8(R2IN)
RS232_RX8_: J54.2 L41.2
RS232_TX6: L43.1 U42.14(T1OUT)
RS232_TX6_: J55.3 L43.2
RS232_TX8: L40.1 U42.7(T2OUT)
RS232_TX8_: J54.3 L40.2
RSET0: R183.2 U16.39(RSET)
RSET2: R158.2 U15.31(RSET)
RXD0: R197.1 U17.9(RXD0)
RXD1: R196.1 R211.1 R212.1 U17.10(RXD1)
RXDV: R217.1 U17.8(RXDV)
RXER/FXEN: R210.2 R220.1 U17.28(RXER/FXEN)
RXN: D80.4 J23.6(P6) R206.8
RXP: D80.3 J23.3(P3) R206.7
SARADC0_BOOT: M1.179(SARADC0_BOOT) R1202.1
SARADC0_IN1_KEY/RECOVERY: M1.56(SARADC0_IN1_KEY/RECOVERY) R264.1
SARADC0_IN3: M1.57(SARADC0_IN3)
SARADC0_IN4: M1.58(SARADC0_IN4)
SARADC0_IN5: M1.59(SARADC0_IN5)
SARADC0_IN6: M1.60(SARADC0_IN6)
SARADC0_IN7: M1.61(SARADC0_IN7)
SARADC1_IN0: C272.2 M1.62(SARADC1_IN0) R350.1
SARADC1_IN1: C273.2 M1.63(SARADC1_IN1) R349.1
SARADC1_IN2: C274.2 M1.64(SARADC1_IN2) R348.1
SARADC1_IN3: C275.2 M1.65(SARADC1_IN3) R347.1
SARADC1_IN4: C276.2 M1.66(SARADC1_IN4) R346.1
SARADC1_IN5: C277.2 M1.67(SARADC1_IN5) R345.1
SARADC1_IN6: M1.68(SARADC1_IN6)
SARADC1_IN7: M1.69(SARADC1_IN7)
SD_CD: J6.9(CD) R28.2
SD_CLK: C279.2 J6.5(CLK) R25.2
SDMMC0_CLK: M1.51(SPI1_CLK_M1/UART5_TX_M0/TEST_CL) R25.1
SDMMC0_CMD: J6.3(CMD) M1.52(SPDIF_TX_M2/UART5_RX_M0/SDMMC0_)
SDMMC0_D0: J6.7(DATA0) M1.50(DSM_AUD_LP/SPI1_MOSI_M1/UART7_R)
SDMMC0_D1: J6.8(DATA1) M1.49(DSM_AUD_LN/SPI1_MISO_M1/UART7_T)
SDMMC0_D2: J6.1(DATA2) M1.54(DSM_AUD_RP/PWM10_M0/SPI1_CSN1_M)
SDMMC0_D3: J6.2(CD/DATA3) M1.53(DSM_AUD_RN/PWM11_M0/SPI1_CSN0_M)
SDMMC0_DET_L: M1.171(I2C4_SDA_M1/SDMMC0_DETN/GPIO0_A) R28.1 R431.2
SDMMC1_CLK: M1.43(PWM1_M1/I2S0_MCLK_M1/RGMII_RXCL) R227.1
SDMMC1_CMD: M1.44(PWM0_M1/I2S0_SCLK_M1/RGMII_RXD3) U18.16(SDIO_DATA_CMD)
SDMMC1_D0: M1.48(PWM8_M1/I2S0_SDI0_M1/RGMII_TXD2) U18.18(SDIO_DATA_0)
SDMMC1_D1: M1.47(PWM9_M1/I2S0_SDI1_M1/RGMII_TXD3) U18.19(SDIO_DATA_1)
SDMMC1_D2: M1.46(PWM10_M1/I2S0_SDO0_M1/RGMII_TXC) U18.14(SDIO_DATA_2)
SDMMC1_D3: M1.45(PWM11_M1/I2S0_LRCK_M1/RGMII_RXD) U18.15(SDIO_DATA_3)
SENSER_SCL: R343.2 U20.6(SCL)
SENSER_SDA: R344.2 U20.5(SDA)
SIM_CLK: C62.2 J11.C3(CLK) R55.2 U8.6(CLK)
SIM_DATA: C63.2 J11.C7(DATA) R53.1 R54.2 U8.3(I/O)
SIM_RST: C61.2 J11.C2(RESET) R56.2 R440.1 U8.7(RST)
SNSN: M1.178(SNSN) TP1.1
SNSP: M1.177(SNSP) TP2.1
SPI0_CLK_M0: M1.160(SPI0_CLK_M0/PWM0_M0/UART2_RTSN_) R363.2
SPI0_CLK_M0/PWM0_M0: J44.4 R363.7
SPI0_CSN0_M0: M1.159(SPI0_CSN0_M0/PWM5_M0/UART2_CTSN) R363.1
SPI0_CSN0_M0/PWM5_M0: J44.2 R363.8
SPI0_MISO_M0: M1.162(SPI0_MISO_M0/PWM2_M0/UART6_RTSN) R363.4
SPI0_MISO_M0/PWM2_M0: J44.8 R363.5
SPI0_MOSI_M0: M1.161(SPI0_MOSI_M0/PWM1_M0/UART6_CTSN) R363.3
SPI0_MOSI_M0/PWM1_M0: J44.6 R363.6
SPK_CTL_L: Q5.3(DRAIN) U25.5(M\U\T\E\) U25.12(S\D\)
SPK_EN_H_GPIO4_B6_D: M1.114(UART3_CTSN_M0/SPI2_CLK_M0/I2S1_) R454.1 R1201.1
SPKN_OUT: M1.175(SPKN_OUT) TP5.1
SPKP_OUT: M1.174(SPKP_OUT) TP4.1
SYS_LED_H: R21.1 R415.2 R1173.1
TN: R206.3 U17.4(MDI0-)
TP: R206.4 U17.3(MDI0+)
TP_INT: J13.3 R449.1 U59.4(A3)
TP_INT_L_GPIO0_B6_D: M1.156(PCIE20_WAKEN_M0/I2C2_SDA_M0/GPI) U59.8(B3)
TP_RST: J13.2 U59.5(A4)
TP_RST_L_GPIO0_B5_D: M1.155(PCIE20_PERSTN_M0/I2C2_SCL_M0/GP) U59.7(B4)
TP_SCL: J13.4 R422.1 U59.3(A2)
TP_SDA: J13.5 R421.1 U59.2(A1)
TXN: D80.6 J23.2(P2) R206.6
TXP: D80.1 J23.1(P1) R206.5
UART0_RX_M0_DEBUG: M1.165(JTAG_CPU_MCU_TMS_M0/UART0_RX_M0) R261.1 R463.1
UART0_TX_M0_DEBUG: M1.166(JTAG_CPU_MCU_TCK_M0/UART0_TX_M0) R464.1
UART3_CTSN_M1: M1.82(I2C4_SCL_M0/SPI0_CSN1_M1/UART3_) R239.2 U18.41(UART_RTS_N)
UART3_RTSN_M1: M1.79(UART3_RTSN_M1/ISP_FLASH_TRIGIN/) U18.44(UART_CTS_N)
UART3_RX_M1: M1.80(SPI0_MISO_M1/UART3_RX_M1/I2S1_S) U18.42(UART_TXD)
UART3_TX_M1: M1.81(I2C4_SDA_M0/SPI0_CSN0_M1/UART3_) U18.43(UART_RXD)
UART4_RX: J44.5 R369.2
UART4_RX_M0: M1.92(UART3_RTSN_M0/UART4_RX_M0/I2S1_) R369.1
UART4_TX: J44.3 R368.2
UART4_TX_M0: M1.91(UART4_TX_M0/I2S1_SDI0_M0/VO_LCD) R368.1
UART6_RX: J44.9 R371.2 R1167.1
UART6_RX_: R1167.2 U42.12(R1OUT)
UART6_RX_M0: M1.164(UART6_RX_M0/CAN0_RX_M2/GPIO0_C7) R371.1 R1208.1
UART6_TX: J44.7 R370.2 U42.11(T1IN)
UART6_TX_M0: M1.163(UART6_TX_M0/CAN0_TX_M2/GPIO0_C6) R370.1 R1207.1
UART8_RX: J44.13 R365.7 R1166.1
UART8_RX_: R1166.2 U42.9(R2OUT)
UART8_RX_M0: M1.85(UART8_RX_M0/CAM_CLK1_OUT_M0/I2S) R365.2
UART8_TX: J44.11 R365.8 U42.10(T2IN)
UART8_TX_M0: M1.86(UART8_TX_M0/CAM_CLK0_OUT_M0/I2S) R365.1
UART9_RX_M1: M1.77(I2C5_SDA_M0/UART9_RX_M1/ISP_FLA) R365.4
UART9_TX_M1: M1.78(I2C5_SCL_M0/UART9_TX_M1/ISP_PRE) R365.3
USB20_HOST1_DM: M1.22(USB20_HOST1_DM) U7.30(DMU)
USB20_HOST1_DP: M1.23(USB20_HOST1_DP) U7.31(DPU)
USB30_OTG0_DM: M1.18(USB30_OTG0_DM) R247.1
USB30_OTG0_DP: M1.19(USB30_OTG0_DP) R248.1
USB30_OTG0_ID: M1.20(USB30_OTG0_ID) Q6.3(DRAIN)
USB30_OTG0_SSRXN/PCIE20_RXDN: M1.27(USB30_OTG0_SSRXN/PCIE20_RXDN) R406.1 R1204.1
USB30_OTG0_SSRXP/PCIE20_RXDP: M1.26(USB30_OTG0_SSRXP/PCIE20_RXDP) R405.1 R1203.1
USB30_OTG0_SSTXN/PCIE20_TXDN: C354.2 M1.25(USB30_OTG0_SSTXN/PCIE20_TXDN) R1205.1
USB30_OTG0_SSTXP/PCIE20_TXDP: C353.2 M1.24(USB30_OTG0_SSTXP/PCIE20_TXDP) R1206.1
USB30_OTG0_VBUSDET: C347.2 M1.21(USB30_OTG0_VBUSDET) R253.2 R353.2 R445.1
USB_HOST2_PWREN_H: R1168.1 U6.4(EN)
USB_HOST3_PWREN_H: R430.1 R450.1 U4.4(EN)
USB_HOST4_PWREN_H: R451.1 R1082.1 U5.4(EN)
USB_OTG: C261.1 J42.1(VBUS1) R445.2 U29.1(VOUT)
USB_OTG_DET_GPIO0_C0_D: M1.158(GPU_AVS/PWM7_M0/UART2_TX_M0/CAN) R353.1
USB_OTG_DM: D37.2(I/O1) J42.2(1D-) R247.2
USB_OTG_DP: D38.2(I/O1) J42.3(1D+) R248.2
USB_OTG_PWREN: R352.1 R429.1
USB_OTG_PWREN_H: R352.2 R456.1 U29.4(EN)
USB_OTG_SSRXN: D42.2(I/O1) J42.5(RX1-) R410.2
USB_OTG_SSRXP: D41.2(I/O1) J42.6(RX1+) R409.2
USB_OTG_SSTXN: C346.1 D40.2(I/O1) J42.8(TX1-)
USB_OTG_SSTXP: C345.1 D39.2(I/O1) J42.9(TX1+)
USB_PCIE_RXN: R402.1 R410.1 R1204.2
USB_PCIE_RXP: R401.1 R409.1 R1203.2
USB_PCIE_TXN: C317.1 C346.2 R1205.2
USB_PCIE_TXP: C319.1 C345.2 R1206.2
USIM_CLK: J10.12(USIM_CLK) R55.1
VOLN: C216.1 J35.1 L25.2
VOLP: C217.1 J35.2 L26.2
VORN: C220.1 J35.3 L27.2
VORP: C221.1 J35.4 L28.2
WIFI1T1R_CLK: C170.2 R227.2 U18.17(SDIO_DATA_CLK)
WIFI1T1R_XTAL_IN: C167.2 U18.10(XTAL_IN) XT5.3
WIFI1T1R_XTAL_OUT: C171.2 U18.11(XTAL_OUT) XT5.1
WIFI_REG_ON_H: R229.2 R238.1 R246.1
WIFI_REG_ON_H_GPIO0_A0_D: M1.172(REF_CLK_OUT/GPIO0_A0_D) R229.1
WIFIBT_32KIN_1T1R: C180.2 R243.2 U18.24(LPO)
N19354508: C1048.1 R136.1 R137.2 U13.4(ADJ)
N19356461: R132.1 R133.2 U11.4(ADJ)
N19357233: R134.1 R135.2 U12.4(ADJ)
N19411583: J21.14(Y_LED+) R157.1
N19487510: C84.1 Q3.1(GATE) R80.1 R443.2
N19487520: Q4.3(DRAIN) R443.1
N20425490: J21.11(G_LED+) R150.1
N69227900: L3.1 U3.3(SW)
N69227918: C31.1 R8.1 R10.2 U3.5(FB)
N69724413: C37.2 R9.2 U3.1(EN)
N69763264: C1049.1 M1.14(MIC1_IN)
N69763270: C1050.1 M1.13(MIC2_IN)
N69764395: J10.10(USIM_IO) R54.1
N69764397: J10.14(USIM_RESET) R56.1
N69764433: LED2.A(ANODE) R452.1
N69764492: R441.2 U9.1(EN)
N69764501: C79.1 R60.1 R442.2 U9.5(FB)
N69764515: L7.1 U9.3(SW)
N69764582: J10.8(VREG_USIM) R52.1
N69765778: R31.1 U4.3(OCB)
N69765789: R34.1 U5.3(OCB)
N69765908: R439.1 U7.48(OVCB_1)
N69765931: R438.1 U7.36(BUS_B)
N69765961: R435.2 U7.5(OVCB_3)
N69765963: R436.2 U7.7(OVCB_4)
N69774873: R244.2 U18.29(VDD_TCXO)
N69774879: R245.2 R246.2 U18.34(BT_RST_N)
N69774884: C168.2 R225.1 U18.2(WL_BT_ANT)
N69774885: C169.2 J24.2(SIG) R225.2
N69774891: C343.2 C367.2 L13.2 U18.23(VIN_LDO)
N69774914: L13.1 U18.21(VIN_LDO_OUT)
N69774994: R238.2 U18.12(WL_REG_ON)
N69783431: D43.C J28.1
N69783435: J28.2 R464.2
N69783454: D43.A R463.2
N69784782: C189.2 U20.1(OSCI) XT6.1
N69784786: C191.2 U20.2(OSCO) XT6.2
N69784848: D49.A J47.1
N69791555: R434.2 U7.1(OVCB_2)
N69811283: D18.A L8.2 U10.1(LX)
N69811295: R84.1 U10.3(FB)
N69814289: LED1.1(+) R19.2
N69814308: LED1.2(-) Q1.3(DRAIN)
N69814328: Q1.1(GATE) R21.2
N69841804: D1.A D2.A D3.C F3.2 F4.2
N69861791: C82.2 J13.1 R62.2
N69863607: C281.2 R388.1 R465.2
N69863700: C280.2 R387.1 R466.2
N69865878: C223.2 D67.1(I/O2) J37.5(L-COM) R314.1 R455.2
N69867903: L26.1 U25.1(VOLP)
N69867905: L25.1 U25.3(VOLN)
N69867925: L27.1 U25.14(VORN)
N69867927: L28.1 U25.16(VORP)
N69867929: C215.2 R303.1
N69867931: R303.2 U25.7(INL)
N69867938: C219.2 R309.1
N69867940: R309.2 U25.10(INR)
N69867965: C214.2 U25.8(BYPASS)
N69871260: Q5.1(GATE) R446.1 R454.2
N69917404: C369.1 R138.1 R139.2 U14.4(ADJ)
N69923813: C114.2 J21.1(CT1/2/3/4)
N69957333: C147.2 J22.1(CT1/2/3/4)
N69957443: J22.11(G_LED+) R189.1
N69960536: J22.13(Y_LED-) R193.1
N69961030: C163.2 J23.4(P4)
N69961588: C166.2 J23.5(P5)
N69966336: J23.12(Y+) R219.2
N70024964: R341.1 U29.3(OCB)
N70036634: Q6.1(GATE) R456.2
N70058734: R35.1 U6.3(OCB)
N70074623: C265.2 R130.2 U11.3(EN)
N70074833: C266.2 R373.2 U12.3(EN)
N70075015: C267.2 R374.2 U13.3(EN)
N70075198: C268.2 R375.2 U14.3(EN)
N70088511: R448.1 U59.12(OE)
N70100637: R414.1 U7.42(DRV)
N70130938: C339.2 U17.29(DVDD10OUT)
N70140073: Q4.1(GATE) R453.2
N70164941: R787.2 R1060.1 R1061.2 U70.9(FB)
N70165129: R782.2 R783.2 U70.12(EN)
N70165139: C810.1 U70.7(BS)
N70165141: C810.2 L33.1 U70.2(LX)
N70165164: C815.2 R1061.1
N70166760: C1012.1 Q8.1(GATE) R1062.2 R1063.1
N70166762: Q7.3(DRAIN) R1062.1
N70166881: Q7.1(GATE) R4.2
N70177512: R1066.1 R1067.2 U71.4(ADJ)
N70177574: C1014.2 R1065.2 U71.3(EN)
N70177973: R1069.1 R1070.2 U72.4(ADJ)
N70178035: C1018.2 R1068.2 U72.3(EN)
N70190247: C1034.1 Q10.1(GATE) R1079.2 R1080.1
N70190249: Q9.3(DRAIN) R1079.1 R1083.2
N70190329: Q9.1(GATE) R1078.2 R1192.1
N70208813: C282.2 C283.2 D79.A(I/O2) M1.1(VCC5V0_IN1) M1.2(VCC5V0_IN2) R1209.1 R1210.1
N70209347: C1035.2 J10.22(PERST_N)
N70209679: C529.1 U42.1(C1+)
N70209681: C529.2 U42.3(C1-)
N70209685: C527.1 U42.4(C2+)
N70209687: C527.2 U42.5(C2-)
N70209691: C530.1 U42.2(V+)
N70209695: C528.1 U42.6(V-)
N70210897: C1039.1 R1169.2 R1170.1 U73.5(FB)
N70210968: L44.1 U73.3(SW)
N70211090: C1045.2 R1171.2 U73.1(EN)
N70266506: J23.10(G-) R218.2
N70266836: R1200.1 U17.19(TXD3)
N70310222: C533.1 R461.2 R462.2
N70310339: C531.1 R460.1 U43.5(VIO/NC)
N70379039: R1211.2 U18.13(WL_HOST_WAKE)
N76747942: R209.1 U17.1(RSET)
N76750177: C341.2 U17.2(AVDD100UT)

Pads without a net: D33 5; D34 5; D35 5; D36 5; D80 5; J10 1 3 5 6 7 11 13 16 17 19 20 23 25 28 30 31 32 33 44 45 46 47 48 49 51; J11 C6 CD1 CD2; J16 4 19 20; J18 26 30; J19 20 21 23 24; J20 10 18 28; J23 7; J27 5 6 7 8 10 11 13 17 19 20 22 23 24 25 26 28 29 30 31 32 34 35 36 37 38 40 42 44 46 48 56 58 67 69; J37 6; J42 14 15 17 18; J45 2; LED1 3; NOREF 1; NOREF#2 1; NOREF#3 1; NOREF#4 1; NOREF#5 1; NOREF#6 1; U7 2 4 8 38 43 44 45 46 47; U8 2 4 5; U15 27; U16 31; U17 13 18 27; U18 4 5 7 8 25 26 27 28 30 32 35 37 38 39 40 45 46 47; U20 3 7; U70 11

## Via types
v1: diameter 0.55, hole 0.3, TOP to BOTTOM, 1964 vias

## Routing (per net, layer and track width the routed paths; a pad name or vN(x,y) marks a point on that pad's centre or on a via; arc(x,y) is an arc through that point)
GND: length 2255.8
  TOP w0.127: C176.1 128.24,26.95 128.43,27.13 ; C313.1 123.17,52.99 122.35,52.17 115.54,52.17 115.07,51.7 v1(112.94,51.7) ; v1(20.29,16.99) 19.58,17.7 18.36,17.7 v1(17.84,17.18) 16.61,17.18 13.98,14.55 13.98,13.19 13.71,12.92 C97.1 ; R1192.2 32.8,27.59 v1(32.76,27.63) ; v1(97.17,50.27) 96.52,49.61 95.42,49.61 93.24,47.43 93.24,44.49 89.41,40.66 85.95,40.66 v1(85.74,40.45) ; v1(5.55,21.96) 16.13,21.96 v1(16.47,21.62) ; v1(127.9,66.93) 127.42,66.45 126.02,66.45 124.8,65.23 124.8,64.7 123.15,63.05 123.15,60.59 122.64,60.08 ; v1(127.87,55.99) 127.82,56.04 126.92,56.04 124.62,58.34 124.62,59.05 123.89,59.78 123.89,62.54 125.38,64.04 127.47,64.04 v1(127.69,63.81) ; v1(67.6,59.84) 66.85,60.59 66.22,60.59 65.21,61.6 62.87,61.6 62,60.73 62,60.18 62.74,59.44 v1(62.79,59.44) 64.01,58.23 v1(64.01,56.55) 64.01,55.74 66.79,52.95 v1(66.79,52.3) 66.79,51.91 70.69,48.02 70.69,38.71 69.98,38.01 69.98,33.97 v1(69.73,33.71) 69.73,32.16 71.27,30.62 71.27,25.8 v1(71.03,25.56) 71.27,25.32 71.27,24.62 70.43,23.78 70.43,22.73 v1(70.22,22.52) 70.2,22.49 70.2,21.65 v1(70.29,21.56) 70.31,21.53 71.88,21.53 73.19,22.85 v1(73.19,24.71) ; v1(127.79,53.25) 125.51,53.25 122.96,50.7 119.91,50.7 v1(119.29,50.07) ; 69.84,56.94 69.76,57.03 69.76,60.13 69.73,60.15 69.73,61.38 69.87,61.51 M1.55 ; v1(11.84,17.94) 13.85,19.95 v1(17.14,19.95) ; v1(23.02,22.39) 24,21.41 24,19.16 23.05,18.21 14.61,18.21 11.69,15.28 9.11,15.28 8.07,14.24 8.07,12.41 ; v1(45.03,34.94) 42.7,32.62 42.7,26.7 44.75,24.64 56.47,24.64 58.46,22.66 v1(58.46,20.98) 58.46,20.64 60.27,18.83 60.48,18.83
  TOP w0.152: v1(20.29,16.99) 19.99,16.99 19.01,16.01 16.5,16.01 15.2,14.71 C268.1 14.73,13.52 14.73,10.6 16.26,9.06 16.26,8.62 17.21,7.68 J19.16
  TOP w0.203: J19.19 v1(15.71,5.65) ; J20.12 v1(4.22,17.01) 4.22,17.65 4.39,17.81 ; U59.6 13.62,30.26 v1(14.13,29.75) ; J20.30 5.49,20.61 v1(5.57,20.53) ; v1(83.73,59.4) 85.44,59.4 86.56,58.28 86.56,53.03 88.33,51.27 88.81,51.27 v1(88.86,51.21) ; 4.39,17.81 3.59,18.61 J20.19 ; 4.39,17.81 J20.16 ; v1(17.21,5.65) J19.16 ; J19.22 v1(14.21,7.78) 13.94,8.05 13.94,11.22 13.76,11.4 C96.1 ; v1(48.88,8.08) 48.88,7.5 48.71,7.33 J18.4 ; v1(4.22,15.65) 4.38,15.81 J20.6
  TOP w0.254: J18.23 39.21,5.05 v1(39.25,5.01) ; v1(99.65,8.49) 99.44,8.49 98.08,7.13 98.08,1.71 ; U7.10 116.36,45.6 115.73,44.96 v1(115.73,44.86) ; J46.7 v1(7.6,58.12) ; v1(74.02,50.71) 73.28,50.71 72.42,51.57 v1(72.42,52.36) 72.42,53.38 71.55,54.25 71.55,55.23 69.84,56.94 ; v1(74.02,50.71) 74.19,50.71 75.28,51.8 75.28,54.05 74.79,54.54 ; v1(74.02,50.71) 73.16,49.85 73.16,38.11 71.97,36.92 71.97,35.42 72.38,35.02 v1(72.38,34.7) 72.3,34.63 72.3,33.81 73.31,32.8 73.54,32.8 ; Q5.2 104.68,18.95 R446.2 ; v1(64.09,65.36) 63.95,65.5 63.95,65.87 64.7,66.62 64.7,67.75 64.28,68.17 C272.1 ; v1(74.25,83.75) 74.7,84.2 Q1.2 ; v1(73.19,24.71) 74.37,24.71 74.71,25.05 74.71,25.59 v1(74.76,25.64) 74,26.4 74,32.01 73.54,32.47 73.54,32.8 ; J18.25 38.21,5.01 v1(38.21,5.01) ; v1(113.82,46.64) 113.95,46.64 114.19,46.88 U7.16 ; J19.13 v1(18.71,5.65) ; Q4.2 8.8,42.03 v1(9.27,41.56) ; v1(44.19,10.04) 43.75,10.48 43.75,11.68 43.52,11.91 R1178.2 ; J46.4 5.75,56.62 5.49,56.36 v1(5.49,55.91) ; v1(78.82,71.59) 78.82,71.18 77.58,69.93 76.2,69.93 74.27,68 70.91,68 68.94,66.03 v1(68.94,64.65) ; 75.28,60.07 76.41,61.19 v1(76.41,61.55) ; J51.2 86.38,51.89 87.54,50.73 87.54,47.53 87.21,47.21 C271.1 ; U7.37 110.19,41.01 v1(110.06,41.14) ; 73.54,32.8 74.65,33.9 74.65,35.39 74.98,35.73 74.98,36.38 v1(74.96,36.4) 74.96,36.86 75.2,37.09 75.2,48.62 77.86,51.29 77.86,58.18 M1.180 ; v1(57.71,47.79) 57.71,48.85 57.03,49.54 52.72,49.54 v1(52.36,49.18) v1(51.59,49.18) 50.9,49.18 50.4,48.68 49.77,48.68 v1(49.27,49.18) ; v1(20.71,4.94) 20.21,5.44 J19.10 ; v1(44.13,5.01) 44.21,5.09 J18.13 ; v1(23.02,22.39) 22.51,22.9 v1(22.51,24.23) 22.51,27.85 21.29,29.07 20.73,29.07 19.9,28.23 8.71,28.23 v1(7.82,27.34) ; 38.74,23.17 v1(38.74,26.7) 38.78,26.74 38.78,34.84 40.13,36.2 40.13,40.76 41.58,42.2 v1(42.7,42.2) 43.1,42.6 45.71,42.6 46.51,41.79 54.72,41.79 55.58,42.65 ; v1(61.25,8.54) 58.83,8.54 58.54,8.83 v1(58.54,10.83) 58.54,12.73 58.8,12.99 v1(61.25,12.99) ; v1(125.51,31.58) 125.56,31.53 129.3,31.53 129.7,31.13 129.7,30.26 v1(129.32,29.88) 129.7,29.5 129.7,27.67 129.17,27.13 125.69,27.13 v1(125.64,27.19) ; J46.1 5.53,55.12 v1(5.49,55.15) ; J18.10 v1(45.71,5.65) ; U7.33 109.61,42.6 v1(110.06,43.04) ; v1(16.92,42.83) 17.06,42.97 Q7.2 ; U7.40 111.69,40.82 111.92,41.05 v1(111.92,41.18) ; v1(32.76,27.63) 32.71,27.68 Q9.2 ; J18.18 41.71,5.17 v1(41.87,5.01) ; J46.10 v1(7.6,59.62) ; D39.1 92.26,71.46 91.81,71.46 90.33,69.98 90.33,63.66 v1(90.2,63.53) ; v1(82.57,69.31) 82.57,69.71 81.77,70.51 80.97,70.51 75.11,76.38 v1(75.11,78.06) 74.91,78.26 74.91,81 75.22,81.31 79.47,81.31 J42.21 ; J18.1 50.21,5.61 ; Q6.2 91.48,63.65 91.85,63.28 v1(91.98,63.28) ; v1(7.87,61.29) 7.69,61.12 J46.13 ; J10.40 102.38,56.7 103.03,56.05 v1(103.03,55.79) 102.63,55.39 102.63,52 105.44,49.18 108.87,49.18 109.63,48.42 109.63,47.02 v1(110.06,46.6) U7.25 ; J10.34 104.78,56.39 104.68,56.29 v1(104.68,55.84) 104.68,51.59 106.23,50.05 110.55,50.05 v1(110.65,49.94) 110.83,49.94 111.19,49.59 U7.22 ; U7.6 116.24,43.6 v1(115.73,43.09) ; J18.7 v1(47.21,5.65) ; J18.16 42.71,5.11 v1(42.81,5.01) ; v1(47.91,49.18) 44.14,49.18 43.64,48.68 43.33,48.68 42.77,49.24 v1(42.77,51.72) 42.25,52.25 39.09,52.25 v1(38.83,52.51) 38.83,52.51 v1(38.83,53.19)
  TOP w0.381: v1(19.21,58.07) 19.52,57.76 R1060.2 ; J10.27 v1(107.58,67.34) ; v1(94.44,24.58) 94.58,24.44 C214.1 R306.2 ; C217.2 81.78,6.64 v1(81.14,7.27) ; J10.21 v1(109.98,64.24) ; C268.1 v1(15.2,13.39) R139.1 ; D37.1 75.47,78.42 v1(75.11,78.06) ; J10.43 v1(101.18,64.07) ; v1(122.26,50.31) v1(120.56,50.31) 119.92,49.68 C54.2 ; v1(122.26,50.31) 122.98,49.59 XT1.2 ; v1(122.26,50.31) 123.74,50.31 123.98,50.07 v1(123.98,48.14) 123.98,46.01 123.73,45.75 v1(122.21,45.75) ; v1(15.27,59.47) D24.3 D24.8 ; 37.57,53.19 v1(38.83,53.19) ; v1(63.28,9.68) 63.24,9.73 U20.4 ; 126.78,27.13 126.77,27.15 XT5.2 ; J10.35 v1(104.38,64.17) ; v1(9.43,17.77) 9.34,17.86 C288.1 C1028.1 ; C94.1 41.31,12.05 v1(40.53,12.83) ; J10.15 v1(115.58,64.07) ; v1(50.58,66.6) C147.1 C131.1 ; J10.9 v1(117.98,64.17) ; R782.1 R785.1 21.43,56.06 v1(21.62,56.25) ; v1(91.85,48.56) 92.23,48.94 R442.1 ; v1(122.21,45.75) v1(120.71,45.75) 120.3,45.75 119.92,46.13 C53.1 ; v1(122.21,45.75) 122.21,45.81 XT1.4 ; R10.1 v1(25.43,32.16) ; R135.1 26.83,18.83 v1(26.55,19.11) 26.55,19.46 26.93,19.84 C266.1 ; C36.1 33,36.82 v1(33.05,36.88) C95.1 ; v1(111.07,15.36) 110.81,15.36 110.42,14.97 U42.15 ; C189.1 v1(61.25,12.99) ; v1(129.32,29.88) 129.06,29.62 128.89,29.62 128.57,29.94 XT5.4 ; v1(49.25,68.85) 49.56,68.53 C270.1 ; v1(26.19,32.16) 26.19,32.6 C37.1 ; J10.37 v1(103.58,64.17) ; C284.2 15.91,32.44 v1(16.38,31.97) ; J10.50 v1(98.38,59.18) ; J10.4 v1(119.98,58.98) ; C114.1 v1(67.02,70.18) ; C1045.1 v1(106.87,26.07) ; C150.2 v1(34.83,73.95) ; C166.1 v1(22.95,68.36) ; v1(9.64,34.07) 10.16,33.56 C285.1 ; R1169.1 v1(106.87,25.05) ; R218.1 v1(34.83,74.96) ; C190.2 68.81,11.84 68.81,12.16 v1(68.74,12.22) ; C112.2 v1(56.42,66.6) ; C191.1 v1(61.25,8.54) ; C269.1 31.6,23.78 31.04,24.35 v1(31.04,24.8) ; J10.29 v1(106.78,67.34) ; v1(107.55,59.01) 107.98,58.58 J10.26 ; C152.1 v1(34.83,71.91) ; R200.1 v1(34.83,72.93)
  TOP w0.508: v1(79.76,59.09) 79.55,58.88 M1.180 78.56,59.77 v1(78.87,60.08) ; v1(125.93,24.52) 125.51,24.94 C344.1 ; C216.2 79.41,6.95 v1(79.41,7.4) ; 6.51,79.72 J1.3 ; J1.3 7.49,81.4 ; J1.3 5.53,81.4 ; J16.14 12.45,58.01 ; J16.14 10.79,58.01 ; J16.14 11.62,57.18 ; R447.1 121.9,74.43 D66.2 v1(121.93,75.27) ; C1018.1 31.59,11.17 31.61,11.14 ; J1.2 11.71,83.08 ; J1.2 10.73,81.4 ; J1.2 12.69,81.4 ; J1.2 11.71,79.72 ; C1037.1 v1(104.53,22.26) ; C167.1 125.51,27.31 v1(125.64,27.19) ; v1(78.15,66.79) 78.65,67.28 C279.1 ; J56.4 132.17,33.53 ; J56.4 131.39,32.75 ; J56.4 132.17,31.97 ; J56.4 132.95,32.75 ; C221.2 75.4,6.44 75.94,5.9 v1(75.94,5.55) ; 129.35,88.98 SW4.3 ; SW4.3 131.01,88.98 ; SW4.3 130.18,88.15 ; 131.34,67.42 J7.4 ; J7.4 132.11,66.64 ; J7.4 132.11,68.2 ; J42.22 93.6,83.87 ; J42.22 92.02,82.3 ; J42.22 95.17,82.3 ; 13.62,49.18 J16.5 ; J16.5 13.62,50.83 ; J16.5 12.79,50.01 ; v1(104.81,19.59) 104.81,19.13 R446.2 ; v1(111.08,23.35) 109.89,23.35 109.31,22.77 R244.1 ; C814.2 21.43,57.51 v1(20.86,58.07) ; D6.1 127.89,53.15 v1(127.79,53.25) ; 78.88,76.62 J42.20 ; J42.20 80.46,75.04 ; J42.20 80.46,78.19 ; J42.20 82.03,76.62 ; v1(116.19,68.41) 115.87,68.41 C280.1 ; C171.1 125.47,30.92 125.47,31.54 v1(125.51,31.58) ; U18.33 111.52,18.9 111.11,19.31 111.11,20.7 v1(111.11,20.7) U18.31 ; v1(94.01,20.81) C209.1 ; 87.03,78.06 J42.7 ; J42.7 87.03,79.53 ; J42.7 86.29,78.8 ; J42.7 87.76,78.8 ; D68.2 v1(117.61,75.45) ; J22.10 37.75,75.52 ; J22.10 36.81,74.58 ; J22.10 38.69,74.58 ; J22.10 37.75,73.64 ; C366.1 v1(111.92,33.74) ; v1(109.25,28.86) 109.31,28.8 C343.1 C180.1 ; D79.C 86.49,21.11 84.97,21.11 v1(84.49,20.63) ; 11.98,88.6 J1.5 ; J1.5 12.66,87.17 ; J1.5 13.34,88.6 ; SW4.2 128.63,87.86 ; SW4.2 127.8,87.03 ; SW4.2 129.46,87.03 ; SW4.2 128.63,86.2 ; J6.6 v1(109.42,77.21) ; C69.1 v1(106.01,53.65) ; D46.2 v1(78.16,81.98) ; J1.6 3.54,88.6 ; J1.6 2.18,88.6 ; J1.6 2.86,87.17 ; C1035.1 v1(109.76,52.95) ; C220.2 v1(77.56,7.33) ; J21.10 58.25,74.58 ; J21.10 57.31,75.52 ; J21.10 56.37,74.58 ; J21.10 57.31,73.64 ; C1033.1 v1(30.32,26.45) ; 131.34,55.99 J8.4 ; J8.4 132.11,55.21 ; J8.4 132.11,56.77 ; C303.1 v1(121.23,44.86) ; v1(31.97,11.14) 31.61,11.14 ; 31.61,11.14 31.59,11.11 R1070.1 ; 2.7,34.51 J43.2 ; J43.2 3.48,35.29 ; J43.2 2.7,36.07 ; 84.26,80.3 J42.4 82.79,80.3 ; C1029.1 9.3,21.11 v1(9.68,20.73) 9.05,20.1 C1030.1 ; M6.1 123.52,13.62 ; M6.1 121.44,11.54 ; M6.1 119.37,13.62 ; M6.1 121.44,15.7 ; C208.1 C207.1 v1(99.73,19.34) ; v1(130.21,42.7) 130.1,42.81 J28.3 ; C76.1 v1(108.74,52.95) ; 12.79,58.01 J16.13 13.62,58.83 ; v1(112.7,15.4) 112.62,15.4 C1036.1 ; J16.6 12.45,50.01 ; J16.6 10.79,50.01 ; J16.6 11.62,49.18 ; U18.36 v1(115.19,16.58) ; J55.4 97.03,2.9 ; J55.4 96.25,2.12 ; J55.4 95.47,2.9 ; C170.1 v1(117.18,31.98) ; C355.1 120.87,42.11 120.96,42.2 120.96,42.22 120.98,42.24 120.98,42.28 v1(120.96,42.3) ; C311.1 v1(104.93,41.54) ; C113.2 73.64,71.73 v1(73.39,71.49) ; C356.1 v1(119.29,50.07) ; 93.6,75.04 J42.19 92.02,76.62 ; C264.1 122.65,9.43 v1(122.21,9.43) ; 85.19,2.9 J54.4 ; J54.4 86.74,2.9 ; J54.4 85.96,2.12 ; 87.76,75.6 J42.16 87.03,74.86 ; C223.1 124.05,74.04 124.08,74.07 D67.2 v1(124.08,75.45) ; U18.20 v1(115.19,30.11) ; D69.2 v1(115.45,73.67) ; C342.1 v1(113.19,32.67) ; 82.03,82.3 J42.21 78.88,82.3 ; J43.1 3.48,37.29 ; J43.1 2.7,38.07 ; J43.1 2.7,36.51 ; v1(88.38,27.8) 87.74,27.16 R389.1 C302.1 ; C306.1 v1(104.93,42.55) ; 19.72,71.23 J23.8 ; J23.8 20.53,72.04 ; J23.8 18.91,72.04 ; J23.8 19.72,72.85 ; D4.1 v1(127.69,63.81) ; C67.1 v1(105.89,67.52) ; R316.1 v1(119.74,75.45) ; D5.2 v1(127.9,66.93)
  TOP w1.016: 16.39,37.12 J27.G3 18.82,39.54
  L2-VCC w0.508: SW4.3 131.01,88.98 ; SW4.3 130.18,88.15 ; SW4.3 129.35,88.98 ; J54.4 85.96,3.67 ; J54.4 85.96,2.12 ; J54.4 85.19,2.9 ; J54.4 86.74,2.9 ; 11.98,88.6 J1.5 ; J1.5 13.34,88.6 ; J1.5 12.66,87.17 ; 11.62,49.33 J16.6 ; J16.6 11.62,50.68 ; J16.6 12.3,50.01 ; J16.6 10.94,50.01 ; 86.29,78.8 J42.7 ; J42.7 87.03,78.06 ; J42.7 87.03,79.53 ; J42.7 87.76,78.8 ; 11.62,57.33 J16.14 ; J16.14 10.94,58.01 ; J16.14 11.62,58.68 ; J16.14 12.3,58.01 ; J42.21 80.46,83.87 ; J42.21 80.46,80.72 ; J42.21 78.88,82.3 ; J42.21 82.03,82.3 ; J21.10 57.31,75.52 ; J21.10 56.37,74.58 ; J21.10 57.31,73.64 ; J21.10 58.25,74.58 ; 13.62,49.33 J16.5 ; J16.5 12.94,50.01 ; J16.5 13.62,50.68 ; J42.16 87.03,76.33 ; J42.16 87.76,75.6 ; J42.16 86.29,75.6 ; J42.16 87.03,74.86 ; 96.25,2.12 J55.4 ; J55.4 97.03,2.9 ; J55.4 95.47,2.9 ; J55.4 96.25,3.67 ; 99.98,3.45 J44.19 ; J44.19 98.95,4.48 ; J44.19 99.98,5.51 ; J44.19 101.01,4.48 ; J22.10 37.75,75.52 ; J22.10 38.69,74.58 ; J22.10 37.75,73.64 ; J22.10 36.81,74.58 ; 12.94,58.01 J16.13 ; J16.13 13.62,58.68 ; J16.13 13.62,57.33 ; J16.13 14.3,58.01 ; J8.4 132.11,56.77 ; J8.4 132.89,55.99 ; J8.4 131.34,55.99 ; J8.4 132.11,55.21 ; 127.8,87.03 SW4.2 ; SW4.2 129.46,87.03 ; SW4.2 128.63,86.2 ; SW4.2 128.63,87.86 ; 78.88,76.62 J42.20 ; J42.20 80.46,78.19 ; J42.20 82.03,76.62 ; J42.20 80.46,75.04 ; J42.13 84.26,77.1 ; J42.13 82.79,77.1 ; J42.13 83.53,76.36 ; J42.13 83.53,77.83 ; J42.22 95.17,82.3 ; J42.22 93.6,80.72 ; J42.22 92.02,82.3 ; J42.22 93.6,83.87 ; J42.19 93.6,78.19 ; J42.19 92.02,76.62 ; J42.19 93.6,75.04 ; 19.72,71.23 J23.8 ; J23.8 20.53,72.04 ; J23.8 19.72,72.85 ; J23.8 18.91,72.04 ; J42.4 83.53,81.03 ; J42.4 84.26,80.3 ; J42.4 83.53,79.56 ; J42.4 82.79,80.3 ; M6.1 121.44,15.05 ; M6.1 122.87,13.62 ; M6.1 120.02,13.62 ; M6.1 121.44,12.19 ; J56.4 132.95,32.75 ; J56.4 132.17,31.97 ; J56.4 132.17,33.53 ; J56.4 131.39,32.75 ; J1.6 3.54,88.6 ; J1.6 2.86,87.17 ; J1.6 2.18,88.6 ; 10.73,81.4 J1.2 ; J1.2 11.71,79.72 ; J1.2 12.69,81.4 ; J1.2 11.71,83.08 ; 132.11,66.64 J7.4 ; J7.4 132.11,68.2 ; J7.4 132.89,67.42 ; J7.4 131.34,67.42
  L2-VCC w1.016: J27.G3 18.82,39.04 ; J27.G3 18.82,35.19 ; J27.G3 20.86,37.12 ; J27.G3 16.89,37.12
  L3-GND w0.508: J43.2 2.7,36.07 ; J43.2 1.92,35.29 ; J43.2 3.48,35.29 ; J43.2 2.7,34.51 ; 10.94,50.01 J16.6 ; J16.6 11.62,49.33 ; J16.6 11.62,50.68 ; J16.6 12.3,50.01 ; J23.8 20.53,72.04 ; J23.8 19.72,72.85 ; J23.8 18.91,72.04 ; J23.8 19.72,71.23 ; 86.29,75.6 J42.16 ; J42.16 87.03,74.86 ; J42.16 87.76,75.6 ; J42.16 87.03,76.33 ; J42.21 80.46,83.87 ; J42.21 82.03,82.3 ; J42.21 80.46,80.72 ; J42.21 78.88,82.3 ; 11.71,79.72 J1.2 ; J1.2 11.71,83.08 ; J1.2 12.69,81.4 ; J1.2 10.73,81.4 ; 10.94,58.01 J16.14 ; J16.14 11.62,57.33 ; J16.14 11.62,58.68 ; J16.14 12.3,58.01 ; J1.5 13.34,88.6 ; J1.5 11.98,88.6 ; J1.5 12.66,87.17 ; J1.6 3.54,88.6 ; J1.6 2.18,88.6 ; J1.6 2.86,87.17 ; J54.4 86.74,2.9 ; J54.4 85.96,3.67 ; J54.4 85.96,2.12 ; J54.4 85.19,2.9 ; 83.53,76.36 J42.13 ; J42.13 82.79,77.1 ; J42.13 83.53,77.83 ; J42.13 84.26,77.1 ; 93.6,80.72 J42.22 ; J42.22 95.17,82.3 ; J42.22 93.6,83.87 ; J42.22 92.02,82.3 ; J55.4 97.03,2.9 ; J55.4 96.25,3.67 ; J55.4 95.47,2.9 ; J55.4 96.25,2.12 ; J21.10 58.25,74.58 ; J21.10 57.31,73.64 ; J21.10 56.37,74.58 ; J21.10 57.31,75.52 ; 120.02,13.62 M6.1 ; M6.1 121.44,15.05 ; M6.1 121.44,12.19 ; M6.1 122.87,13.62 ; 131.34,55.99 J8.4 ; J8.4 132.11,56.77 ; J8.4 132.11,55.21 ; J8.4 132.89,55.99 ; 12.94,58.01 J16.13 ; J16.13 13.62,58.68 ; J16.13 13.62,57.33 ; J16.13 14.3,58.01 ; J7.4 132.11,68.2 ; J7.4 132.11,66.64 ; J7.4 131.34,67.42 ; J7.4 132.89,67.42 ; J16.5 13.62,50.68 ; J16.5 12.94,50.01 ; J16.5 13.62,49.33 ; J42.7 87.76,78.8 ; J42.7 86.29,78.8 ; J42.7 87.03,79.53 ; J42.7 87.03,78.06 ; J43.1 2.7,38.07 ; J43.1 3.48,37.29 ; J43.1 1.92,37.29 ; J43.1 2.7,36.51 ; J1.3 7.49,81.4 ; J1.3 6.51,83.08 ; J1.3 5.53,81.4 ; J1.3 6.51,79.72 ; J42.4 84.26,80.3 ; J42.4 83.53,79.56 ; J42.4 83.53,81.03 ; J42.4 82.79,80.3 ; 131.39,32.75 J56.4 ; J56.4 132.95,32.75 ; J56.4 132.17,31.97 ; J56.4 132.17,33.53 ; 127.8,87.03 SW4.2 ; SW4.2 128.63,86.2 ; SW4.2 128.63,87.86 ; SW4.2 129.46,87.03 ; 37.75,73.64 J22.10 ; J22.10 38.69,74.58 ; J22.10 36.81,74.58 ; J22.10 37.75,75.52 ; 93.6,75.04 J42.19 ; J42.19 93.6,78.19 ; J42.19 92.02,76.62 ; 80.46,75.04 J42.20 ; J42.20 78.88,76.62 ; J42.20 82.03,76.62 ; J42.20 80.46,78.19 ; 18.82,35.19 J27.G3 ; J27.G3 20.75,37.12 ; J27.G3 18.82,39.04 ; J27.G3 16.89,37.12 ; SW4.3 131.01,88.98 ; SW4.3 130.18,88.15 ; SW4.3 129.35,88.98 ; 99.98,3.45 J44.19 ; J44.19 98.95,4.48 ; J44.19 101.01,4.48 ; J44.19 99.98,5.51
  BOTTOM w0.127: v1(77.37,22.38) 78.32,22.38 84.15,16.55 v1(84.73,16.55) ; v1(69.04,58.65) 69.04,58.97 68.91,59.1 66.92,59.1 v1(66.71,59.31) ; v1(70.29,21.56) 70.4,21.45 76.01,21.45 76.64,20.81 77.96,20.81 83.62,15.15 83.71,15.15 83.77,15.08 85.16,13.7 85.16,11.61 87.71,9.06 93.01,9.06 93.67,9.72 96.14,9.72 v1(96.39,9.47) 96.91,9.47 97.88,8.49 v1(99.65,8.49) 99.65,8.11 99.78,7.98 103.14,7.98 v1(103.43,8.28) 103.43,8.58 102.5,9.52 101.89,9.52 100.8,10.61 98.1,10.61 97.34,11.37 90.21,11.37 89.93,11.09 88.58,11.09 87.92,11.75 v1(87.92,12.35) v1(87.92,12.99) 87.92,13.37 87.91,13.37 v1(85.7,15.58) ; v1(64.01,56.55) 64.01,54.68 64.49,54.2 64.49,49.45 64.88,49.05 v1(65.56,49.05) ; v1(30.13,53.88) 29.62,53.37 R1198.1 ; v1(70.22,22.52) 70.48,22.52 71.47,23.5 72.3,23.5 72.65,23.15 76.62,23.15 v1(76.9,22.87) ; 89.36,30.45 89.36,30.57 v1(89.28,30.65) v1(88.78,31.15) 88.35,31.15 85.58,33.92 84.97,33.92 82.23,36.66 75.23,36.66 v1(74.96,36.4) ; v1(117.25,11.64) 117.25,11.7 116.36,12.59 115.4,12.59 114.76,13.23 113.19,13.23 v1(111.07,15.36) 109.98,15.36 109.57,15.76 103.15,15.76 102.33,16.59 91.59,16.59 86.97,21.21 86.53,21.21 84.14,23.6 83.33,23.6 78.77,28.15 72.05,28.15 71.24,27.34 69.36,27.34 69.3,27.29 v1(69.3,27.28) ; v1(71.03,25.56) 71.61,25.56 72.66,26.61 78.16,26.61 82.75,22.02 83.1,22.02 v1(83.55,21.58) 83.67,21.58 83.69,21.55 83.69,21.43 v1(84.02,21.1) 84.49,20.63 v1(84.49,20.63) 85.44,19.68 86.08,19.68 90.7,15.06 101.7,15.06 102.52,14.24 108.53,14.24 111.06,11.71 114.13,11.71 115.18,10.66 v1(115.18,10.36) ; 91.7,50.6 90.52,49.42 90.52,48.38 90.8,48.11 91.18,48.11 91.64,48.56 v1(91.85,48.56) ; v1(104.53,22.26) 103.99,22.8 93.67,22.8 88.68,27.8 v1(88.38,27.8) 88.38,27.82 82.53,33.66 72.7,33.66 72.3,34.06 72.3,34.63 v1(72.38,34.7) ; v1(110.78,9.72) 110.34,9.72 107.47,12.59 101.84,12.59 101.08,13.35 90.08,13.35 85.4,18.03 84.47,18.03 78.07,24.44 73.46,24.44 v1(73.19,24.71) 72.79,25.1 72.79,25.67 72.98,25.85 77.79,25.85 84.72,18.92 85.77,18.92 90.44,14.25 101.43,14.25 102.2,13.48 107.84,13.48 110.49,10.83 112.05,10.83 v1(112.55,10.32) ; v1(103.63,25.05) 103.42,24.83 95.26,24.83 94.75,25.34 94.15,25.34 89.87,29.63 90.2,29.63 v1(90.2,29.62) 90.2,29.73 ; v1(94.46,46.76) 94.26,46.96 v1(90.6,46.96) v1(89.45,46.96) ; XT2.2 67.13,55 65.53,55 65.37,55.15 65.37,58.01 65.62,58.26 XT2.4 ; v1(42.76,35.16) 42.39,35.53 42.39,35.84 38.32,39.91 36.47,39.91 34.99,41.38 26.84,41.38 26.13,40.68 21.52,40.68 20.81,41.38
  BOTTOM w0.152: XT3.2 47.45,55.76 45.82,55.76 45.7,55.88 45.7,58.64 46.08,59.02 XT3.4 46.5,59.2 47.17,59.87 49.21,59.87 49.56,59.52 C128.1
  BOTTOM w0.203: v1(44.19,10.04) 44.19,8.65 42.67,7.14 42.67,7.1 ; 20.42,25.22 16.96,25.22 v1(16,24.25) 15.65,23.91 15.65,22.43 v1(16.47,21.62) 16.5,21.58 16.5,20.58 v1(17.14,19.95) 17.84,19.25 v1(17.84,17.18) 18.88,18.22 24.57,18.22 25.24,18.88 26.32,18.88 v1(26.55,19.11) ; v1(42.88,61.16) 42.88,60.66 43.79,59.76 43.79,50.8 48.97,45.62 50.33,45.62 52.45,43.5 55.93,43.5 v1(56.26,43.83) v1(60.18,43.83) 60.63,43.83 65.56,48.76 v1(65.56,49.05) 65.86,48.76 74.44,48.76 75.69,50.01 76.35,50.01 76.48,50.14 76.48,51.51 77.08,52.11 v1(77.08,52.37) ; v1(110.65,49.94) 110.6,49.99 105.87,49.99 105.3,50.57 100.07,50.57 v1(99.85,50.35) 99.85,50.36 99.54,50.36 95.26,54.63 95.26,59.76 94.85,60.17 94.85,62.69 94.27,63.28 v1(91.98,63.28) ; v1(78.82,71.59) 79,71.77 80.17,71.77 v1(81.29,72.88) v1(81.8,73.39) 81.9,73.49 v1(84.36,73.49) v1(85.25,73.49) v1(86.14,73.49) v1(88.48,73.49) v1(89.36,73.49) 94.05,73.49 94.89,74.33 94.89,74.36 97.71,77.18 99.93,77.18 100.89,78.14 v1(107.22,78.14) 111.39,78.14 111.97,77.55 v1(111.97,77.38) 111.97,76.82 111.35,76.2 107.28,76.2 105.73,74.65 v1(102.52,74.65) 98.47,74.65 94.61,70.78 v1(91.96,70.78) v1(89.49,70.78) 89.02,70.78 88.76,70.52 ; C151.1 82.27,52.1 80.8,50.63 ; J27.51 v1(102.09,40.37) 102.62,40.9 102.62,42.31 101.95,42.98 100.52,42.98 98.41,45.1 98.41,47.85 97.95,48.31 v1(97.95,48.94) 97.6,49.28 93.53,49.28 92.81,48.56 v1(91.85,48.56) ; v1(112.05,51.32) 107.88,51.32 107.24,51.95 106.06,51.95 v1(105.82,51.72) v1(100.49,51.72) v1(99.85,51.72) 99.42,51.72 96.24,54.91 96.24,60.07 95.82,60.48 95.82,63.14 88.76,70.21 88.76,70.52 ; 88.76,70.52 88.5,70.77 v1(88.27,70.77) v1(85.45,70.77) 84.03,70.77 v1(82.57,69.31) 82.57,69.29 80.95,67.66 v1(80.95,67.6) 80.95,62.4 80.59,62.05 80.59,61.14 C363.1 ; v1(94.46,46.76) 94.46,47.04 94.5,47.07 94.5,47.38 95.34,48.22 96.5,48.22 97.59,47.13 97.59,44.38 96.17,44.38 95.84,44.04 93.62,44.04 93.12,44.54 93.12,45.42 92.67,45.88 v1(91.85,45.88) ; v1(80.06,48.36) 80.02,48.36 79.99,48.33 79.99,48.29 79.97,48.27 79.81,48.27 79.67,48.12 79.67,47.84 v1(79.65,47.82) 79.64,47.81 79.64,47.71 79.66,47.68 79.76,47.68 79.85,47.59 79.85,47.42 79.69,47.25 v1(79.69,46.59) 79.46,46.59 78.49,45.61 77.59,45.61 v1(77.28,45.31) 76.98,45 66.94,45 61.71,39.77 v1(60.05,39.77) v1(55.15,39.77) v1(49.93,39.77) 49.67,39.77 44.8,44.65 42.44,44.65 40.99,46.1 38.08,46.1 37.1,47.08 34.52,47.08 ; v1(44.13,5.01) v1(42.81,5.01) v1(41.87,5.01) v1(39.25,5.01) v1(38.21,5.01) 36.66,5.01 35.99,4.34 v1(29.2,4.34) v1(28.46,4.34) v1(27.77,4.34) v1(25.1,4.34) v1(24.43,4.34) 24.07,4.34 24.06,4.35 v1(19.46,4.35) v1(17.97,4.35) 17.3,4.35 16.92,4.73 16.92,5.37 v1(17.21,5.65) 17.21,6.18 17.9,6.87 21.21,6.87 21.7,6.38 v1(31.78,6.38) v1(32.67,6.38) v1(33.69,6.38) v1(34.83,6.38) ; 100.11,41.87 J27.57 ; v1(89.02,57.56) 89.19,57.39 89.19,51.4 89.01,51.21 v1(88.86,51.21) 88.04,51.21 85.6,48.77 85.6,44.77 v1(85.73,44.64) 85.73,43.12 v1(85.76,43.09) 85.74,43.07 v1(85.74,41.63) v1(85.74,40.45) 85.74,40.3 v1(86.55,39.49) 86.98,39.06 88.39,39.06 v1(88.83,39.49) 89.07,39.49 89.6,40.02 91.5,40.02 92.23,40.75 93.03,40.75 93.29,41.02 93.29,42.36 93.43,42.5 95.21,42.5 96.48,41.23 96.48,40.74 99.4,37.82 99.21,37.82 v1(99.14,37.75) 99.19,37.75 99.58,37.37 J27.39 ; v1(39.53,22.38) v1(41.6,20.31)
  BOTTOM w0.254: v1(35.13,28.23) 34.53,27.63 v1(32.76,27.63) 31.12,27.63 30.32,26.84 v1(30.32,26.45) 30.32,25.64 28.92,24.23 v1(22.51,24.23) 22.51,24.49 21.78,25.22 20.42,25.22 ; J27.9 101.77,29.87 102.01,30.11 v1(102.01,31) ; v1(102.08,37.71) 101.74,37.37 J27.39 ; v1(20.29,16.99) 20.68,17.38 24.92,17.38 25.58,18.04 26.9,18.04 27.03,18.17 37.55,18.17 v1(37.77,18.39) 37.98,18.17 39.91,18.17 40.62,18.88 v1(40.62,19.34) v1(41.6,20.31) ; v1(99.14,37.75) 99.4,37.5 99.4,36.41 99.94,35.87 J27.33 ; v1(44.13,5.01) 46.57,5.01 v1(47.21,5.65) 47.69,5.65 48.88,6.84 v1(48.88,8.08) 48.88,9.12 v1(47.32,10.68) ; v1(59.72,68.87) 58.45,70.14 55.66,70.14 53.84,71.96 53.84,74.04 51.97,75.9 50.45,75.9 49.36,76.99 46.54,76.99 45.78,77.76 v1(45.5,77.76) 45.14,77.4 v1(43.72,77.4) v1(41.31,77.4) 40.32,77.4 37.75,74.84 J22.10 37.75,71.64 39.38,70.01 v1(41.56,70.01) ; v1(35.97,63.66) 35.97,66.33 v1(36.1,66.45) 36.1,67.77 33.61,70.26 33.61,71.52 28.95,76.18 21.22,76.18 19.72,74.68 J23.8 21.35,70.41 30.01,70.41 32.04,68.38 v1(32.04,67.47) ; 109.99,27.69 111.47,27.69 114.72,30.94 116.14,30.94 v1(117.18,31.98) 117.82,32.62 119.87,32.62 120.3,32.19 v1(120.3,31.99) 120.93,31.36 120.93,29.36 118.52,26.95 v1(117.77,26.95) 117.76,26.96 v1(114.21,26.96) 113.81,26.96 109.58,22.73 105.46,22.73 104.99,22.26 v1(104.53,22.26) ; v1(78.23,64.55) 78.15,64.63 v1(78.15,66.79) 78.15,68.31 73.17,73.29 72.42,73.29 67.95,77.76 v1(65.31,77.76) v1(63.41,77.76) v1(61.37,77.76) 60.48,77.76 J21.10 57.31,71.53 57.82,71.03 61.17,71.03 62.09,70.1 63.49,70.1 64.19,69.4 66.24,69.4 v1(67.02,70.18) 68.1,69.1 68.38,69.1 68.74,68.74 68.74,65.95 68.94,65.74 v1(68.94,64.65) ; v1(99.17,31.39) 99.19,31.37 J27.15 ; v1(42.77,51.72) 42.85,51.8 42.85,55.64 v1(42.7,55.79) 42.7,58.17 v1(42.45,58.43) ; J27.45 v1(102.1,38.87) ; v1(26.55,19.11) 30.03,19.11 v1(30.13,19.21) ; J27.27 99.51,34.37 ; v1(17.63,61.05) 17.18,60.59 17.18,54.64 v1(17.05,54.52) 17.05,54.13 16.49,53.58 16.49,50.06 17.1,49.45 v1(17.1,47.79) v1(17.1,47.11) 17.1,45.09 20.81,41.38 ; C158.1 26.07,59.98 25.8,60.24 v1(25.8,61.24) 25.8,63.78 26.19,64.17 30,64.17 30.39,63.79 30.39,61.55 31.1,60.84 31.27,60.84 v1(31.38,60.74) ; 46.21,68.51 47.39,69.69 48.58,69.69 48.79,69.9 50.27,69.9 50.58,69.59 v1(50.58,66.6) 50.61,66.57 v1(50.61,64.28) 50.41,64.28 50.15,64.02 v1(50.15,63.63) ; 100.11,41.87 99.8,41.87 v1(99.6,42.07) 99.6,42.37 97.59,44.38 ; v1(33.94,45.37) v1(36.46,45.37) 37.23,44.6 40.16,44.6 42.21,42.55 43.69,42.55 44.23,42.01 v1(44.23,41.56) ; J27.21 99.62,32.87
  BOTTOM w0.305: v1(52.3,64.18) 52.29,64.17 C330.1
  BOTTOM w0.381: XT2.4 66.19,58.79 v1(66.71,59.31) ; v1(40.29,56.42) C338.1 R216.2 ; C328.1 v1(61.12,50.96) ; C318.1 76.99,52.68 77.08,52.6 v1(77.08,52.37) ; v1(54.29,50.96) 54.01,51.24 R179.1 ; R211.2 42.43,58.45 v1(42.45,58.43) ; R180.1 55.91,51.06 v1(55.83,50.98) 55.83,50.66 56.11,50.38 C143.1 ; R181.1 v1(56.93,50.98) ; v1(51.63,69.53) v1(51.63,68.85) 52.36,68.13 D36.2 ; v1(34.07,65.36) v1(34.07,66.07) D80.2 ; C82.1 5.11,43.91 v1(5.11,43.47) ; v1(56.42,68.85) D35.2 v1(56.42,66.6) ; v1(50.24,58.5) 50.24,58.71 49.66,59.28 C128.1 ; C151.1 82.51,52.36 83.05,52.9 83.05,53.07 v1(83.53,53.55) ; C155.1 38.7,53.32 v1(38.83,53.19) ; R184.1 v1(58.83,50.96)
  BOTTOM w0.508: J56.4 132.95,32.75 ; J56.4 132.17,31.97 ; J56.4 132.17,33.53 ; J56.4 131.39,32.75 ; C126.2 C321.1 v1(74.02,54.7) ; J1.2 11.71,83.08 ; J1.2 12.69,81.4 ; J1.2 10.73,81.4 ; J1.2 11.71,79.72 ; 87.03,78.06 J42.7 ; J42.7 87.03,79.53 ; J42.7 86.29,78.8 ; J42.7 87.76,78.8 ; J1.3 7.49,81.4 ; J1.3 6.51,79.72 ; J1.3 6.51,83.08 ; J1.3 5.53,81.4 ; v1(115.5,60.51) 115.48,60.48 115.48,59.03 C314.1 ; J42.13 83.53,77.83 ; J42.13 82.79,77.1 ; J42.13 84.26,77.1 ; v1(34.4,50.6) 34.2,50.81 C340.1 ; v1(38.85,49.63) 39.53,49.63 R187.1 ; 78.88,76.62 J42.20 ; J42.20 82.03,76.62 ; J42.20 80.46,78.19 ; J42.20 80.46,75.04 ; 19.72,71.23 J23.8 ; J23.8 20.53,72.04 ; J23.8 18.91,72.04 ; 85.19,2.9 J54.4 ; J54.4 85.96,3.67 ; J54.4 85.96,2.12 ; 128.63,86.2 SW4.2 ; SW4.2 128.63,87.86 ; SW4.2 129.46,87.03 ; SW4.2 127.8,87.03 ; 129.35,88.98 SW4.3 ; SW4.3 130.18,88.15 ; SW4.3 131.01,88.98 ; C320.1 v1(74.02,50.71) ; J42.21 80.46,83.87 ; J42.21 78.88,82.3 ; J42.21 82.03,82.3 ; J42.21 80.46,80.72 ; J1.5 13.34,88.6 ; J1.5 12.66,87.17 ; J1.5 11.98,88.6 ; R209.2 C341.1 v1(32.16,63.53) ; XT3.4 v1(46.5,57.97) ; v1(50.88,50.98) 51.21,51.31 C333.1 ; C158.1 v1(26.51,59.4) ; J42.4 84.26,80.3 ; J42.4 82.79,80.3 ; J42.4 83.53,81.03 ; 16.14,37.12 J27.G3 18.82,39.79 ; v1(81.63,61.91) 81.63,61.44 81.31,61.12 C363.1 ; C156.2 30.61,59.98 v1(31.38,60.74) ; J16.14 11.62,58.83 ; J16.14 12.45,58.01 ; J16.14 11.62,57.18 ; v1(72.42,52.36) 72.17,52.6 C326.1 ; v1(58.54,59.6) 58.72,59.41 C364.1 ; v1(47.56,61.13) 47.57,61.12 C332.1 R183.1 C334.1 ; XT2.2 68.98,55.86 v1(69.12,55.72) C116.2 ; 57.31,75.52 J21.10 56.37,74.58 ; XT4.2 v1(27.98,63.04) ; 121.44,12.19 M6.1 ; M6.1 120.02,13.62 ; M6.1 121.44,15.05 ; 132.11,56.77 J8.4 132.11,55.21 ; J42.22 93.6,83.87 ; J42.22 95.17,82.3 ; J42.22 92.02,82.3 ; J1.6 3.54,88.6 ; J1.6 2.18,88.6 ; J1.6 2.86,87.17 ; C331.1 v1(56.36,63.53) ; 86.29,75.6 J42.16 ; J42.16 87.76,75.6 ; J42.16 87.03,76.33 ; J16.13 14.45,58.01 ; J16.13 12.79,58.01 ; J16.13 13.62,58.83 ; J16.13 13.62,57.18 ; v1(50.24,56.2) 50.09,56.35 C129.1 48.57,56.35 XT3.2 ; C325.1 v1(79.76,59.09) ; C132.1 v1(42.77,51.72) ; XT4.4 v1(25.8,61.24) ; C61.1 v1(113.19,57.56) ; v1(69.04,58.65) C115.2
  vias: v1(0.78,87.92) v1(0.78,86.65) v1(0.78,85.38) v1(0.78,84.11) v1(0.78,82.84) v1(0.78,81.57) v1(0.78,80.3) v1(0.78,79.03) v1(0.78,77.76) v1(0.78,76.49) v1(0.78,75.22) v1(0.78,73.95) v1(0.78,72.68) v1(0.78,71.41) v1(0.78,70.14) v1(0.78,68.87) v1(0.78,67.6) v1(0.78,66.33) v1(0.78,65.06) v1(0.78,63.79) v1(0.78,62.52) v1(0.78,61.25) v1(0.78,59.98) v1(0.78,58.71) v1(0.78,57.44) v1(0.78,56.17) v1(0.78,54.9) v1(0.78,53.8) v1(0.78,52.53) v1(0.78,51.26) v1(0.78,49.99) v1(0.78,48.52) v1(0.78,47.25) v1(0.78,45.98) v1(0.78,44.71) v1(0.78,43.44) v1(0.78,42.17) v1(0.78,40.9) v1(0.78,39.63) v1(0.78,38.36) v1(0.78,37.09) v1(0.78,35.82) v1(0.78,34.55) v1(0.78,33.46) v1(0.78,32.19) v1(0.78,30.92) v1(0.78,29.65) v1(0.78,28.18) v1(0.78,26.91) v1(0.78,25.64) v1(0.78,24.37) v1(0.78,11.84) v1(0.78,10.57) v1(0.78,9.3) v1(0.78,8.03) v1(0.78,6.76) v1(0.78,5.49) v1(0.78,4.22) v1(0.78,3.13) v1(0.79,1.86) v1(1.43,0.94) v1(1.91,89.19) v1(2.83,86.52) v1(2.83,11.59) v1(2.98,21.19) v1(3.06,0.78) v1(3.74,70.24) v1(3.77,89.21) v1(4.1,87.28) v1(4.4,0.78) v1(4.48,86.01) v1(4.73,13.06) v1(5.09,89.21) v1(5.55,22.64) v1(5.75,85.76) v1(5.67,0.78) v1(6.13,67.8) v1(6.13,26.7) v1(6.26,49.31) v1(6.26,48.67) v1(6.23,48.12) v1(6.26,47.53) v1(6.31,52.94) v1(6.74,24.14) v1(6.81,67.8) v1(6.94,0.78) v1(7.27,85.76) v1(7.55,67.81) v1(7.75,89.21) v1(8.03,69.76) v1(8.01,52.99) v1(8.21,0.78) v1(8.67,68.44) v1(8.97,89.21) v1(9.43,12.61) v1(9.48,0.78) v1(9.63,72.09) v1(9.68,26.19) v1(9.81,12.1) v1(9.94,85.76) v1(10.29,89.21) v1(10.27,59.17) v1(10.45,26.19) v1(10.45,12.48) v1(10.75,0.78) v1(10.83,11.97) v1(10.95,11.34) v1(10.95,10.7) v1(11.08,87.92) v1(11.08,84.49) v1(11.08,83.6) v1(11.72,89.21) v1(11.72,86.27) v1(12.1,0.79) v1(12.73,85.88) v1(13.04,30.67) v1(13.11,84.23) v1(13.11,82.07) v1(13.11,80.3) v1(13.16,12.2) v1(13.62,0.79) v1(14.51,39.02) v1(14.87,36.37) v1(15.02,0.79) v1(15.27,39.02) v1(15.63,36.37) v1(16.03,41.05) v1(16.03,40.16) v1(16.14,74.07) v1(16.64,64.34) v1(16.85,22.62) v1(16.92,40.16) v1(17.05,9.99) v1(17.25,64.32) v1(17.18,12.73) v1(17.2,0.82) v1(17.71,56.67) v1(17.69,55.02) v1(17.69,54.13) v1(17.69,52.61) v1(17.69,40.16) v1(17.81,58.07) v1(17.86,71.97) v1(17.86,64.32) v1(17.86,12.72) v1(18.12,83.98) v1(18.32,50.71) v1(18.47,64.29) v1(18.57,31.27) v1(18.63,12.72) v1(18.73,86.7) v1(18.8,23.45) v1(19.11,63.76) v1(19.13,63) v1(19.44,77.91) v1(19.39,12.72) v1(19.46,0.82) v1(20.1,61.63) v1(20.1,60.87) v1(20.08,24.44) v1(20.1,22) v1(20.14,12.72) v1(20.47,46.28) v1(20.86,61.63) v1(20.86,60.87) v1(20.86,59.98) v1(20.86,59.09) v1(20.95,45.8) v1(20.9,12.72) v1(21.3,21.62) v1(21.47,0.82) v1(22.28,73.62) v1(22.51,37.24) v1(22.51,36.48) v1(22.51,35.72) v1(22.59,38.51) v1(23.02,85.63) v1(23.02,83.73) v1(23.02,81.44) v1(23.02,78.65) v1(23.65,53.75) v1(23.69,10.69) v1(24.01,13.42) v1(24.16,45.37) v1(24.29,53.75) v1(24.37,10.69) v1(24.8,45.37) v1(24.92,53.75) v1(25.05,85.63) v1(25.05,83.73) v1(25.05,82.46) v1(25.05,78.65) v1(25.03,0.85) v1(26.07,35.85) v1(26.15,29.92) v1(26.32,13.24) v1(26.7,68.99) v1(26.7,35.85) v1(26.83,29.92) v1(27.01,13.23) v1(27.01,6.46) v1(27.21,55.53) v1(27.21,52.61) v1(27.34,54.9) v1(27.34,54.13) v1(27.34,53.37) v1(27.29,10.9) v1(27.85,32.16) v1(27.77,13.23) v1(28.35,33.69) v1(28.48,32.16) v1(28.53,13.23) v1(28.61,35.85) v1(29.19,12.4) v1(29.67,72.47) v1(29.75,12.4) v1(29.7,0.82) v1(29.85,6.43) v1(30.13,53.33) v1(30.72,53.09) v1(30.77,19.21) v1(31.27,67.47) v1(31.27,66.71) v1(31.27,65.95) v1(31.43,63.51) v1(31.4,19.21) v1(31.91,47.99) v1(31.91,45.75) v1(32.04,66.71) v1(32.04,65.95) v1(32.08,19.21) v1(32.54,47.99) v1(32.6,45.75) v1(32.95,0.82) v1(33.18,47.66) v1(33.18,46.9) v1(33.18,46.13) v1(33.18,45.37) v1(33.21,8.59) v1(33.43,56.8) v1(33.43,55.91) v1(33.84,20.53) v1(33.94,47.66) v1(33.94,46.9) v1(33.94,46.13) v1(34.12,67.88) v1(34.59,11.19) v1(35.08,22.64) v1(35.21,26.7) v1(35.21,24.67) v1(35.34,58.58) v1(35.34,57.69) v1(35.34,56.8) v1(35.34,55.91) v1(35.3,30.94) v1(35.27,11.19) v1(35.91,11.19) v1(35.98,30.96) v1(36.35,24.67) v1(36.43,26.68) v1(36.48,22.64) v1(36.48,20.61) v1(36.53,11.16) v1(36.86,66.45) v1(37.12,0.82) v1(37.24,64.42) v1(37.61,66.45) v1(37.72,10.43) v1(39.15,20.35) v1(39.89,21.37) v1(40.47,52.03) v1(40.67,0.82) v1(41.56,86.27) v1(41.56,84.36) v1(41.56,82.07) v1(41.56,79.28) v1(41.56,40.24) v1(42.03,38.59) v1(42.25,57.82) v1(42.58,64.29) v1(42.98,69.35) v1(43.34,64.29) v1(43.47,86.27) v1(43.47,84.36) v1(43.47,82.07) v1(43.47,79.28) v1(43.59,63.66) v1(43.62,19.54) v1(43.59,15.44) v1(43.73,38.77) v1(43.85,66.83) v1(43.78,36.76) v1(44.23,40.8) v1(44.25,15.44) v1(44.27,63.66) v1(44.36,39.91) v1(44.61,66.83) v1(44.99,37.88) v1(45.5,86.27) v1(45.5,84.36) v1(45.5,82.07) v1(45.5,79.28) v1(46.21,13.9) v1(46.26,39.66) v1(46.69,0.85) v1(46.85,64.12) v1(46.77,20.35) v1(47.03,9.78) v1(47.15,66.71) v1(47.15,52.56) v1(47.28,54.01) v1(47.91,66.71) v1(47.91,54.01) v1(48.59,49.18) v1(48.67,13.9) v1(48.67,5.44) v1(48.98,20.35) v1(50.28,10.95) v1(50.4,19.41) v1(50.83,11.08) v1(50.83,0.85) v1(50.86,73.29) v1(50.95,46.46) v1(51.39,6.26) v1(52.09,73.31) v1(52.36,10.95) v1(52.61,50.96) v1(53.12,58.07) v1(53.12,56.93) v1(53.38,44.03) v1(53.44,5.93) v1(53.75,10.7) v1(54.39,58.07) v1(54.39,56.93) v1(54.39,10.7) v1(54.72,74.94) v1(54.9,6.13) v1(55.15,45.12) v1(55.15,10.7) v1(55.25,0.85) v1(55.66,58.07) v1(55.66,56.93) v1(55.69,46) v1(55.91,10.7) v1(56.45,4.99) v1(56.67,10.7) v1(56.8,6.13) v1(57.21,4.99) v1(57.44,10.7) v1(57.82,8.41) v1(57.86,45.5) v1(57.97,4.99) v1(59.55,61.4) v1(60.13,0.78) v1(60.48,16.67) v1(60.61,68.87) v1(61.25,16.67) v1(61.37,86.01) v1(61.37,84.11) v1(61.37,81.82) v1(61.37,79.03) v1(61.4,0.78) v1(61.63,68.87) v1(61.88,9.18) v1(62.39,68.87) v1(62.47,16.52) v1(62.52,9.18) v1(62.67,0.78) v1(63.15,68.87) v1(63.28,86.01) v1(63.28,84.11) v1(63.28,81.82) v1(63.28,79.03) v1(63.94,0.78) v1(65.18,16.16) v1(65.21,0.78) v1(65.31,86.01) v1(65.31,84.11) v1(65.31,81.82) v1(65.31,79.03) v1(65.95,16.16) v1(66.48,0.78) v1(66.71,16.16) v1(67.47,16.16) v1(67.61,60.52) v1(67.75,0.78) v1(68.74,52.86) v1(68.77,52.18) v1(68.94,63.86) v1(69.12,4.99) v1(69.88,4.99) v1(70.01,9.68) v1(70.64,4.99) v1(70.67,71.29) v1(71.28,9.68) v1(71.37,66.62) v1(72.04,66.62) v1(72.19,71.52) v1(72.58,74.07) v1(72.68,59.47) v1(72.68,58.45) v1(72.68,57.44) v1(73.03,16.67) v1(73.69,89.19) v1(73.69,59.47) v1(73.69,58.45) v1(73.69,57.44) v1(73.82,66.71) v1(73.82,64.93) v1(74.71,89.21) v1(74.71,59.47) v1(74.71,58.45) v1(74.71,57.44) v1(75.47,15.44) v1(75.7,20.98) v1(75.91,66.62) v1(75.98,89.21) v1(76.23,15.44) v1(76.51,66.94) v1(76.74,47.4) v1(77.25,89.21) v1(77.48,0.78) v1(78.06,78.82) v1(78.34,89.21) v1(78.26,75.22) v1(78.57,0.78) v1(79.28,86.27) v1(79.41,12.73) v1(79.41,12.1) v1(79.61,89.21) v1(79.64,47.2) v1(79.87,0.78) v1(80.04,74.45) v1(80.88,89.21) v1(80.88,63.91) v1(81.05,54.05) v1(81.06,79.03) v1(81.12,69.27) v1(81.32,0.78) v1(81.69,86.27) v1(82.15,89.21) v1(82.58,0.78) v1(83.01,67.14) v1(83.42,89.21) v1(83.47,64.29) v1(83.54,57.15) v1(83.68,0.78) v1(83.85,84.74) v1(84.11,82.58) v1(84.27,8) v1(84.57,56.04) v1(84.57,55.28) v1(84.57,54.52) v1(84.69,89.21) v1(84.74,68.61) v1(84.87,61.63) v1(85,8) v1(84.97,0.78) v1(85.21,16.07) v1(85.38,63.79) v1(85.76,8) v1(85.96,89.21) v1(86.01,84.74) v1(86.01,69.33) v1(86.37,63.3) v1(86.42,0.78) v1(87.23,89.21) v1(87.54,82.58) v1(87.54,62.01) v1(88.18,69.63) v1(88.17,63.53) v1(88.42,57.56) v1(88.5,89.21) v1(88.93,58.2) v1(89.06,0.79) v1(89.44,84.74) v1(89.77,89.21) v1(90.18,69.32) v1(91.04,89.21) v1(90.96,86.9) v1(90.96,82.58) v1(91.04,0.79) v1(92.31,89.21) v1(92.44,48.57) v1(92.49,52.74) v1(92.51,30.06) v1(92.51,29.39) v1(92.84,54.36) v1(92.84,51.06) v1(92.87,84.74) v1(92.96,31.55) v1(92.96,30.87) v1(93.05,0.79) v1(93.12,52.74) v1(93.25,86.9) v1(93.5,67.85) v1(93.5,67.09) v1(93.48,51.06) v1(93.58,89.21) v1(93.58,63.1) v1(94.85,89.21) v1(94.9,67.09) v1(95.03,0.79) v1(95.06,50.59) v1(95.66,67.09) v1(96.12,89.21) v1(96.17,82.2) v1(96.3,84.74) v1(96.3,69.5) v1(96.43,67.09) v1(96.43,66.2) v1(96.43,65.44) v1(96.38,0.79) v1(96.55,86.9) v1(96.48,71.1) v1(97.06,69.5) v1(97.39,89.21) v1(97.7,26.45) v1(97.72,0.79) v1(97.82,69.5) v1(98.33,62.14) v1(98.33,26.45) v1(98.65,12.37) v1(98.66,89.21) v1(98.9,78.33) v1(98.92,26.5) v1(99.09,0.79) v1(99.33,12.37) v1(99.37,48.39) v1(99.54,31.95) v1(99.57,30.83) v1(99.66,78.33) v1(99.85,82.2) v1(99.93,89.21) v1(99.93,48.45) v1(99.98,84.74) v1(100,12.37) v1(100.11,69.25) v1(100.67,48.34) v1(100.68,12.37) v1(100.79,69.25) v1(101.12,86.9) v1(101.2,89.21) v1(101.25,48.55) v1(101.28,0.79) v1(101.51,69.25) v1(101.86,46.13) v1(101.86,45.52) v1(102.17,44.74) v1(102.17,43.9) v1(102.47,89.21) v1(103.01,71.66) v1(103.16,82.2) v1(103.28,84.74) v1(103.28,71.03) v1(103.54,62.14) v1(103.54,60.99) v1(103.74,89.21) v1(103.79,0.79) v1(104.31,25.06) v1(104.55,86.9) v1(104.53,48.6) v1(104.5,47.53) v1(104.53,46.59) v1(104.53,45.65) v1(104.58,44.64) v1(104.63,29.9) v1(104.93,79.66) v1(104.93,59.09) v1(105.01,89.21) v1(106.08,82.2) v1(106.2,84.74) v1(106.28,89.21) v1(106.31,0.79) v1(106.59,25.56) v1(106.74,31.68) v1(106.94,27.85) v1(107.04,70.98) v1(107.09,86.9) v1(107.35,50.45) v1(107.55,89.21) v1(107.6,79.66) v1(107.73,30.36) v1(107.83,70.98) v1(108.41,30.49) v1(108.74,82.2) v1(108.82,89.21) v1(108.85,0.79) v1(109.13,30.36) v1(110.09,89.21) v1(110.06,44.82) v1(110.27,79.66) v1(110.4,35.76) v1(111.08,35.75) v1(111.36,89.21) v1(111.41,82.2) v1(111.51,0.79) v1(111.77,35.76) v1(111.92,57.69) v1(111.92,56.93) v1(111.92,46.64) v1(111.92,44.86) v1(111.92,43.09) v1(112.55,86.9) v1(112.63,89.21) v1(112.58,32.32) v1(112.94,68.74) v1(112.94,67.34) v1(112.94,65.95) v1(112.94,64.17) v1(113.27,79) v1(113.32,77.38) v1(113.42,23.12) v1(113.44,19.26) v1(113.82,44.86) v1(113.82,43.09) v1(113.82,41.18) v1(113.9,89.21) v1(114,0.79) v1(114.21,77.38) v1(114.54,79.97) v1(115.17,89.21) v1(115.22,19.21) v1(115.45,26.98) v1(115.73,46.64) v1(115.73,41.18) v1(116.01,24.82) v1(116.29,11.64) v1(116.44,89.21) v1(116.64,83.07) v1(116.57,26.98) v1(116.7,77.5) v1(116.83,0.8) v1(117.15,63) v1(117.63,18.96) v1(117.71,89.21) v1(118.35,58.96) v1(118.37,0.78) v1(119.13,58.99) v1(119.62,0.79) v1(119.67,33.31) v1(119.79,87.92) v1(119.82,31.05) v1(120.05,63.02) v1(120.17,18.96) v1(120.4,81.19) v1(120.43,33.31) v1(120.68,87.92) v1(120.81,59.09) v1(120.92,0.78) v1(121.09,77.83) v1(121.57,87.92) v1(121.6,86.6) v1(121.57,59.09) v1(122.13,27.54) v1(122.08,0.79) v1(122.33,59.09) v1(122.46,87.92) v1(122.46,67.22) v1(123.22,67.22) v1(123.34,0.79) v1(123.48,84.49) v1(123.48,82.46) v1(123.86,18.32) v1(123.98,67.22) v1(124.06,89.21) v1(124.75,20.86) v1(124.75,18.57) v1(124.87,13.88) v1(124.95,0.78) v1(125.13,14.51) v1(125.25,84.36) v1(125.25,82.46) v1(125.33,89.21) v1(125.51,13.88) v1(125.64,18.57) v1(126.12,63.43) v1(126.12,52.71) v1(126.14,49.96) v1(126.14,49.28) v1(126.24,59.95) v1(126.22,0.78) v1(126.26,60.63) v1(126.27,20.86) v1(126.52,18.57) v1(126.6,89.21) v1(126.65,27.21) v1(126.78,86.77) v1(127.21,80.7) v1(127.16,20.86) v1(127.41,18.57) v1(127.49,0.78) v1(127.87,89.21) v1(127.87,80.73) v1(128.05,20.86) v1(128.3,18.57) v1(128.76,0.78) v1(128.94,34.58) v1(129.14,89.21) v1(129.06,20.86) v1(129.24,60.32) v1(129.19,18.57) v1(129.28,60.99) v1(129.26,49.73) v1(129.28,49.04) v1(129.32,31.4) v1(129.45,27.08) v1(129.45,26.45) v1(129.55,80.2) v1(129.7,85.76) v1(129.7,83.85) v1(129.83,21.11) v1(130.03,0.78) v1(130.08,18.57) v1(130.21,21.75) v1(130.33,17.81) v1(130.46,12.22) v1(130.97,22.26) v1(131.1,17.43) v1(131.22,89.21) v1(131.49,0.78) v1(131.86,22.26) v1(131.99,16.16) v1(132.11,39.02) v1(132.21,81.34) v1(132.16,59.16) v1(132.37,17.43) v1(132.49,89.21) v1(132.62,22.26) v1(132.72,36.32) v1(132.72,35.64) v1(133.13,0.82) v1(133.51,43.09) v1(133.51,39.91) v1(133.61,89.03) v1(134.04,1.68) v1(134.2,87.33) v1(134.2,85.61) v1(134.2,81.85) v1(134.2,80.7) v1(134.2,79.03) v1(134.2,77.33) v1(134.2,75.65) v1(134.2,73.97) v1(134.2,72.3) v1(134.2,70.77) v1(134.2,69.63) v1(134.2,47.64) v1(134.2,46.37) v1(134.2,45.1) v1(134.2,43.83) v1(134.2,42.56) v1(134.2,41.29) v1(134.2,40.02) v1(134.2,38.75) v1(134.2,37.48) v1(134.2,36.21) v1(134.2,34.94) v1(134.2,33.67) v1(134.2,32.4) v1(134.2,31.13) v1(134.2,29.86) v1(134.2,28.59) v1(134.2,27.32) v1(134.2,26.05) v1(134.2,24.78) v1(134.2,23.51) v1(134.2,22.24) v1(134.22,20.64) v1(134.22,18.92) v1(134.22,17.46) v1(134.22,16.19) v1(134.22,14.92) v1(134.22,13.65) v1(134.22,12.38) v1(134.22,11.11) v1(134.22,9.84) v1(134.22,8.57) v1(134.22,7.3) v1(134.22,6.03) v1(134.22,4.76) v1(134.22,3.49)
